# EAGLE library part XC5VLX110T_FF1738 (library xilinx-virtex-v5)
xc5vlx110t_ff1738 edit this description Auto generated by make-symbol-device-package-bsdl.ulp Rev. 21 Source: xc5vlx110t_ff1738.bsd
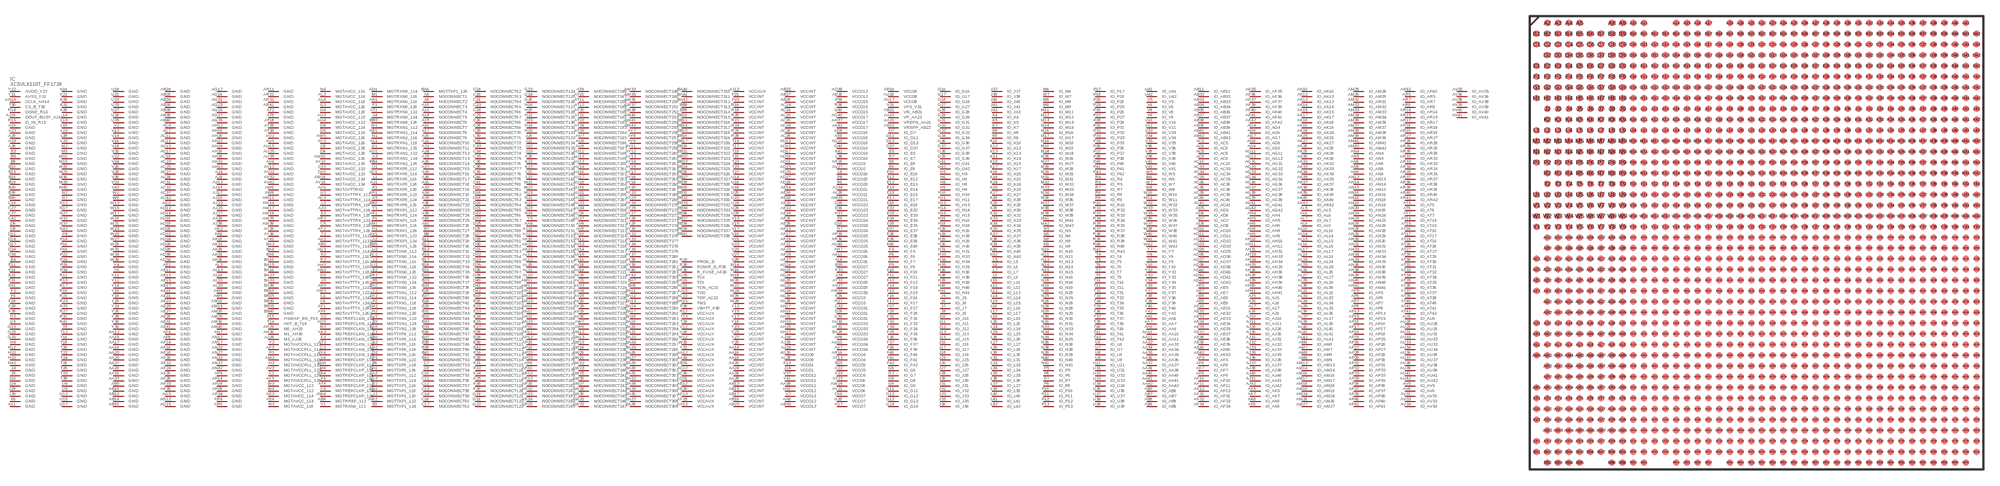
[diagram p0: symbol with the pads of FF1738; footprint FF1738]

Designator prefix IC

## XC5VLX110T_FF1738 (OC_FARNELL: unknown; OC_NEWARK: unknown)  [FF1738]
A2  MGTRXP1_124  pas
A3  MGTRXN1_124  pas
A4  MGTRXN0_124  pas
A5  MGTRXP0_124  pas
A8  NOCONNECT1  pas
A9  NOCONNECT2  pas
A10  NOCONNECT3  pas
A11  NOCONNECT4  pas
A14  NOCONNECT5  pas
A15  NOCONNECT6  pas
A16  NOCONNECT7  pas
A17  NOCONNECT8  pas
A19  GND  pwr
A20  NOCONNECT9  pas
A21  NOCONNECT10  pas
A22  NOCONNECT11  pas
A23  GND  pwr
A24  NOCONNECT12  pas
A25  NOCONNECT13  pas
A26  NOCONNECT14  pas
A27  NOCONNECT15  pas
A28  GND  pwr
A29  NOCONNECT16  pas
A30  NOCONNECT17  pas
A31  NOCONNECT18  pas
A32  NOCONNECT19  pas
A33  GND  pwr
A34  NOCONNECT20  pas
A35  NOCONNECT21  pas
A36  NOCONNECT22  pas
A37  NOCONNECT23  pas
A38  GND  pwr
A39  NOCONNECT24  pas
A40  NOCONNECT25  pas
A41  NOCONNECT26  pas
AA2  MGTTXP1_112  pas
AA3  MGTAVTTTX_1122  pas
AA4  NOCONNECT150  pas
AA5  MGTAVTTRXC  pas
AA6  IO_AA6
AA7  IO_AA7
AA8  VCCO12  pwr
AA9  IO_AA9
AA10  IO_AA10
AA11  IO_AA11
AA12  VCCAUX  pwr
AA13  GND  pwr
AA14  VCCINT  pwr
AA15  GND  pwr
AA16  VCCINT  pwr
AA17  GND  pwr
AA18  VCCINT  pwr
AA19  GND  pwr
AA20  VCCINT  pwr
AA21  VREFN_AA21  pas
AA22  VP_AA22  pas
AA23  GND  pwr
AA24  VCCINT  pwr
AA25  GND  pwr
AA26  VCCINT  pwr
AA27  GND  pwr
AA28  VCCINT  pwr
AA29  GND  pwr
AA30  VCCAUX  pwr
AA31  GND  pwr
AA32  IO_AA32
AA33  GND  pwr
AA34  IO_AA34
AA35  IO_AA35
AA36  IO_AA36
AA37  IO_AA37
AA38  VCCO11  pwr
AA39  IO_AA39
AA40  IO_AA40
AA41  IO_AA41
AA42  IO_AA42
AB2  MGTTXP0_114  pas
AB3  MGTAVTTTX_1141  pas
AB4  MGTRREF_112  pas
AB5  GND  pwr
AB6  IO_AB6
AB7  IO_AB7
AB8  IO_AB8
AB9  IO_AB9
AB10  GND  pwr
AB11  IO_AB11
AB12  GND  pwr
AB13  VCCINT  pwr
AB14  GND  pwr
AB15  VCCINT  pwr
AB16  GND  pwr
AB17  VCCINT  pwr
AB18  GND  pwr
AB19  VCCINT  pwr
AB20  GND  pwr
AB21  VN_AB21  pas
AB22  VREFP_AB22  pas
AB23  VCCINT  pwr
AB24  GND  pwr
AB25  VCCINT  pwr
AB26  GND  pwr
AB27  VCCINT  pwr
AB28  GND  pwr
AB29  VCCINT  pwr
AB30  GND  pwr
AB31  VCCAUX  pwr
AB32  IO_AB32
AB33  IO_AB33
AB34  IO_AB34
AB35  VCCO13  pwr
AB36  IO_AB36
AB37  IO_AB37
AB38  IO_AB38
AB39  IO_AB39
AB40  GND  pwr
AB41  IO_AB41
AB42  IO_AB42
AC1  MGTRXP0_114  pas
AC2  MGTTXN0_114  pas
AC3  MGTAVTTRX_114  pas
AC4  GND  pwr
AC5  IO_AC5
AC6  IO_AC6
AC7  GND  pwr
AC8  IO_AC8
AC9  IO_AC9
AC10  IO_AC10
AC11  GND  pwr
AC12  VCCAUX  pwr
AC13  GND  pwr
AC14  VCCINT  pwr
AC15  GND  pwr
AC16  VCCINT  pwr
AC17  GND  pwr
AC18  VCCINT  pwr
AC19  GND  pwr
AC20  VCCINT  pwr
AC21  TDN_AC21  pas
AC22  TDP_AC22  pas
AC23  GND  pwr
AC24  VCCINT  pwr
AC25  GND  pwr
AC26  VCCINT  pwr
AC27  GND  pwr
AC28  VCCINT  pwr
AC29  GND  pwr
AC30  VCCAUX  pwr
AC31  GND  pwr
AC32  GND  pwr
AC33  IO_AC33
AC34  IO_AC34
AC35  IO_AC35
AC36  IO_AC36
AC37  GND  pwr
AC38  IO_AC38
AC39  IO_AC39
AC40  IO_AC40
AC41  IO_AC41
AC42  GND  pwr
AD1  MGTRXN0_114  pas
AD2  GND  pwr
AD3  MGTREFCLKN_114  pas
AD4  MGTREFCLKP_114  pas
AD5  IO_AD5
AD6  IO_AD6
AD7  IO_AD7
AD8  IO_AD8
AD9  VCCO18  pwr
AD10  IO_AD10
AD11  IO_AD11
AD12  GND  pwr
AD13  VCCINT  pwr
AD14  GND  pwr
AD15  VCCINT  pwr
AD16  GND  pwr
AD17  VCCINT  pwr
AD18  GND  pwr
AD19  VCCINT  pwr
AD20  GND  pwr
AD21  VCCINT  pwr
AD22  GND  pwr
AD23  VCCINT  pwr
AD24  GND  pwr
AD25  VCCINT  pwr
AD26  GND  pwr
AD27  VCCINT  pwr
AD28  GND  pwr
AD29  VCCINT  pwr
AD30  GND  pwr
AD31  VCCAUX  pwr
AD32  IO_AD32
AD33  IO_AD33
AD34  GND  pwr
AD35  IO_AD35
AD36  IO_AD36
AD37  IO_AD37
AD38  IO_AD38
AD39  VCCO13  pwr
AD40  IO_AD40
AD41  IO_AD41
AD42  IO_AD42
AE1  MGTRXN1_114  pas
AE2  GND  pwr
AE3  MGTAVCC_114  pwr
AE4  MGTAVCC_114  pwr
AE5  IO_AE5
AE6  VCCO18  pwr
AE7  IO_AE7
AE8  IO_AE8
AE9  IO_AE9
AE10  IO_AE10
AE11  GND  pwr
AE12  VCCAUX  pwr
AE13  GND  pwr
AE14  VCCINT  pwr
AE15  GND  pwr
AE16  VCCINT  pwr
AE17  GND  pwr
AE18  VCCINT  pwr
AE19  GND  pwr
AE20  VCCINT  pwr
AE21  GND  pwr
AE22  VCCINT  pwr
AE23  GND  pwr
AE24  VCCINT  pwr
AE25  GND  pwr
AE26  VCCINT  pwr
AE27  GND  pwr
AE28  VCCINT  pwr
AE29  GND  pwr
AE30  VCCAUX  pwr
AE31  GND  pwr
AE32  IO_AE32
AE33  IO_AE33
AE34  IO_AE34
AE35  IO_AE35
AE36  VCCO13  pwr
AE37  IO_AE37
AE38  IO_AE38
AE39  IO_AE39
AE40  IO_AE40
AE41  GND  pwr
AE42  IO_AE42
AF1  MGTRXP1_114  pas
AF2  MGTTXN1_114  pas
AF3  MGTAVCCPLL_114  pwr
AF4  GND  pwr
AF5  IO_AF5
AF6  IO_AF6
AF7  IO_AF7
AF8  GND  pwr
AF9  IO_AF9
AF10  IO_AF10
AF11  IO_AF11
AF12  IO_AF12
AF13  VCCAUX  pwr
AF14  GND  pwr
AF15  VCCINT  pwr
AF16  GND  pwr
AF17  VCCINT  pwr
AF18  GND  pwr
AF19  VCCINT  pwr
AF20  GND  pwr
AF21  VCCINT  pwr
AF22  GND  pwr
AF23  VCCINT  pwr
AF24  GND  pwr
AF25  VCCINT  pwr
AF26  GND  pwr
AF27  VCCINT  pwr
AF28  GND  pwr
AF29  VCCAUX  pwr
AF30  R_FUSE_AF30  pas
AF31  IO_AF31
AF32  IO_AF32
AF33  GND  pwr
AF34  IO_AF34
AF35  IO_AF35
AF36  IO_AF36
AF37  IO_AF37
AF38  GND  pwr
AF39  IO_AF39
AF40  IO_AF40
AF41  IO_AF41
AF42  IO_AF42
AG2  MGTTXP1_114  pas
AG3  MGTAVTTTX_1142  pas
AG4  IO_AG4
AG5  GND  pwr
AG6  IO_AG6
AG7  IO_AG7
AG8  IO_AG8
AG9  IO_AG9
AG10  VCCO18  pwr
AG11  IO_AG11
AG12  IO_AG12
AG13  GND  pwr
AG14  VCCINT  pwr
AG15  GND  pwr
AG16  VCCINT  pwr
AG17  GND  pwr
AG18  VCCINT  pwr
AG19  GND  pwr
AG20  VCCINT  pwr
AG21  GND  pwr
AG22  VCCINT  pwr
AG23  GND  pwr
AG24  VCCINT  pwr
AG25  GND  pwr
AG26  VCCINT  pwr
AG27  GND  pwr
AG28  VCCINT  pwr
AG29  TCK  in
AG30  VCCO0  pwr
AG31  IO_AG31
AG32  IO_AG32
AG33  IO_AG33
AG34  IO_AG34
AG35  GND  pwr
AG36  IO_AG36
AG37  IO_AG37
AG38  IO_AG38
AG39  IO_AG39
AG40  VCCO17  pwr
AG41  IO_AG41
AG42  IO_AG42
AH2  MGTTXP0_118  pas
AH3  MGTAVTTTX_1181  pas
AH4  IO_AH4
AH5  IO_AH5
AH6  IO_AH6
AH7  VCCO26  pwr
AH8  IO_AH8
AH9  IO_AH9
AH10  IO_AH10
AH11  IO_AH11
AH12  GND  pwr
AH13  VCCAUX  pwr
AH14  CCLK_AH14
AH15  TMS  in
AH16  TDI  in
AH17  VCCINT  pwr
AH18  GND  pwr
AH19  VCCINT  pwr
AH20  GND  pwr
AH21  VCCINT  pwr
AH22  GND  pwr
AH23  VCCINT  pwr
AH24  GND  pwr
AH25  VCCINT  pwr
AH26  GND  pwr
AH27  VCCINT  pwr
AH28  GND  pwr
AH29  M0_AH29  in
AH30  M1_AH30  in
AH31  IO_AH31
AH32  GND  pwr
AH33  IO_AH33
AH34  IO_AH34
AH35  IO_AH35
AH36  IO_AH36
AH37  VCCO17  pwr
AH38  IO_AH38
AH39  IO_AH39
AH40  IO_AH40
AH41  IO_AH41
AH42  GND  pwr
AJ1  MGTRXP0_118  pas
AJ2  MGTTXN0_118  pas
AJ3  MGTAVTTRX_118  pas
AJ4  GND  pwr
AJ5  IO_AJ5
AJ6  IO_AJ6
AJ7  IO_AJ7
AJ8  IO_AJ8
AJ9  GND  pwr
AJ10  IO_AJ10
AJ11  IO_AJ11
AJ12  VCCAUX  pwr
AJ13  GND  pwr
AJ14  GND  pwr
AJ15  TDO  out
AJ16  DOUT_BUSY_AJ16  out
AJ17  GND  pwr
AJ18  VCCINT  pwr
AJ19  GND  pwr
AJ20  VCCINT  pwr
AJ21  NOCONNECT151  pas
AJ22  NOCONNECT152  pas
AJ23  GND  pwr
AJ24  VCCINT  pwr
AJ25  GND  pwr
AJ26  IO_AJ26
AJ27  GND  pwr
AJ28  M2_AJ28  in
AJ29  GND  pwr
AJ30  IO_AJ30
AJ31  IO_AJ31
AJ32  IO_AJ32
AJ33  IO_AJ33
AJ34  VCCO21  pwr
AJ35  IO_AJ35
AJ36  IO_AJ36
AJ37  IO_AJ37
AJ38  IO_AJ38
AJ39  GND  pwr
AJ40  IO_AJ40
AJ41  IO_AJ41
AJ42  IO_AJ42
AK1  MGTRXN0_118  pas
AK2  GND  pwr
AK3  MGTREFCLKN_118  pas
AK4  MGTREFCLKP_118  pas
AK5  IO_AK5
AK6  GND  pwr
AK7  IO_AK7
AK8  IO_AK8
AK9  IO_AK9
AK10  IO_AK10
AK11  VCCO26  pwr
AK12  IO_AK12
AK13  IO_AK13
AK14  IO_AK14
AK15  IO_AK15
AK16  GND  pwr
AK17  IO_AK17
AK18  IO_AK18
AK19  IO_AK19
AK20  NOCONNECT153  pas
AK21  GND  pwr
AK22  NOCONNECT154  pas
AK23  NOCONNECT155  pas
AK24  IO_AK24
AK25  IO_AK25
AK26  GND  pwr
AK27  IO_AK27
AK28  IO_AK28
AK29  IO_AK29
AK30  IO_AK30
AK31  GND  pwr
AK32  IO_AK32
AK33  IO_AK33
AK34  IO_AK34
AK35  IO_AK35
AK36  GND  pwr
AK37  IO_AK37
AK38  IO_AK38
AK39  IO_AK39
AK40  IO_AK40
AK41  VCCO17  pwr
AK42  IO_AK42
AL1  MGTRXN1_118  pas
AL2  GND  pwr
AL3  MGTAVCC_118  pwr
AL4  MGTAVCC_118  pwr
AL5  IO_AL5
AL6  IO_AL6
AL7  IO_AL7
AL8  VCCO26  pwr
AL9  IO_AL9
AL10  IO_AL10
AL11  NOCONNECT156  pas
AL12  NOCONNECT157  pas
AL13  GND  pwr
AL14  IO_AL14
AL15  IO_AL15
AL16  IO_AL16
AL17  IO_AL17
AL18  GND  pwr
AL19  IO_AL19
AL20  NOCONNECT158  pas
AL21  NOCONNECT159  pas
AL22  NOCONNECT160  pas
AL23  GND  pwr
AL24  IO_AL24
AL25  IO_AL25
AL26  IO_AL26
AL27  IO_AL27
AL28  VCCO0  pwr
AL29  IO_AL29
AL30  IO_AL30
AL31  IO_AL31
AL32  IO_AL32
AL33  GND  pwr
AL34  IO_AL34
AL35  IO_AL35
AL36  IO_AL36
AL37  IO_AL37
AL38  VCCO21  pwr
AL39  IO_AL39
AL40  IO_AL40
AL41  IO_AL41
AL42  IO_AL42
AM1  MGTRXP1_118  pas
AM2  MGTTXN1_118  pas
AM3  MGTAVCCPLL_118  pwr
AM4  GND  pwr
AM5  GND  pwr
AM6  IO_AM6
AM7  IO_AM7
AM8  IO_AM8
AM9  IO_AM9
AM10  GND  pwr
AM11  NOCONNECT161  pas
AM12  NOCONNECT162  pas
AM13  IO_AM13
AM14  IO_AM14
AM15  GND  pwr
AM16  IO_AM16
AM17  IO_AM17
AM18  IO_AM18
AM19  IO_AM19
AM20  GND  pwr
AM21  NOCONNECT163  pas
AM22  NOCONNECT164  pas
AM23  NOCONNECT165  pas
AM24  IO_AM24
AM25  GND  pwr
AM26  IO_AM26
AM27  IO_AM27
AM28  IO_AM28
AM29  IO_AM29
AM30  GND  pwr
AM31  IO_AM31
AM32  IO_AM32
AM33  IO_AM33
AM34  IO_AM34
AM35  VCCO21  pwr
AM36  IO_AM36
AM37  IO_AM37
AM38  IO_AM38
AM39  IO_AM39
AM40  GND  pwr
AM41  IO_AM41
AM42  IO_AM42
AN2  MGTTXP1_118  pas
AN3  MGTAVTTTX_1182  pas
AN4  IO_AN4
AN5  IO_AN5
AN6  IO_AN6
AN7  GND  pwr
AN8  IO_AN8
AN9  IO_AN9
AN10  NOCONNECT166  pas
AN11  NOCONNECT167  pas
AN12  GND  pwr
AN13  IO_AN13
AN14  IO_AN14
AN15  IO_AN15
AN16  IO_AN16
AN17  GND  pwr
AN18  IO_AN18
AN19  IO_AN19
AN20  IO_AN20
AN21  NOCONNECT168  pas
AN22  GND  pwr
AN23  NOCONNECT169  pas
AN24  IO_AN24
AN25  IO_AN25
AN26  IO_AN26
AN27  GND  pwr
AN28  IO_AN28
AN29  IO_AN29
AN30  IO_AN30
AN31  IO_AN31
AN32  GND  pwr
AN33  IO_AN33
AN34  IO_AN34
AN35  IO_AN35
AN36  IO_AN36
AN37  GND  pwr
AN38  IO_AN38
AN39  IO_AN39
AN40  IO_AN40
AN41  IO_AN41
AN42  GND  pwr
AP2  MGTTXP0_122  pas
AP3  MGTAVTTTX_1221  pas
AP4  GND  pwr
AP5  IO_AP5
AP6  IO_AP6
AP7  IO_AP7
AP8  IO_AP8
AP9  VCCO34  pwr
AP10  NOCONNECT170  pas
AP11  NOCONNECT171  pas
AP12  NOCONNECT172  pas
AP13  IO_AP13
AP14  GND  pwr
AP15  IO_AP15
AP16  IO_AP16
AP17  IO_AP17
AP18  IO_AP18
AP19  VCCO8  pwr
AP20  NOCONNECT173  pas
AP21  NOCONNECT174  pas
AP22  NOCONNECT175  pas
AP23  NOCONNECT176  pas
AP24  GND  pwr
AP25  IO_AP25
AP26  IO_AP26
AP27  IO_AP27
AP28  IO_AP28
AP29  GND  pwr
AP30  IO_AP30
AP31  IO_AP31
AP32  IO_AP32
AP33  IO_AP33
AP34  GND  pwr
AP35  IO_AP35
AP36  IO_AP36
AP37  IO_AP37
AP38  IO_AP38
AP39  VCCO25  pwr
AP40  IO_AP40
AP41  IO_AP41
AP42  IO_AP42
AR1  MGTRXP0_122  pas
AR2  MGTTXN0_122  pas
AR3  MGTAVTTRX_122  pas
AR4  GND  pwr
AR5  IO_AR5
AR6  GND  pwr
AR7  IO_AR7
AR8  IO_AR8
AR9  NOCONNECT177  pas
AR10  NOCONNECT178  pas
AR11  GND  pwr
AR12  NOCONNECT179  pas
AR13  NOCONNECT180  pas
AR14  IO_AR14
AR15  IO_AR15
AR16  VCCO4  pwr
AR17  IO_AR17
AR18  IO_AR18
AR19  IO_AR19
AR20  NOCONNECT181  pas
AR21  GND  pwr
AR22  NOCONNECT182  pas
AR23  NOCONNECT183  pas
AR24  NOCONNECT184  pas
AR25  NOCONNECT185  pas
AR26  VCCO2  pwr
AR27  IO_AR27
AR28  IO_AR28
AR29  IO_AR29
AR30  IO_AR30
AR31  GND  pwr
AR32  IO_AR32
AR33  IO_AR33
AR34  IO_AR34
AR35  IO_AR35
AR36  VCCO25  pwr
AR37  IO_AR37
AR38  IO_AR38
AR39  IO_AR39
AR40  IO_AR40
AR41  GND  pwr
AR42  IO_AR42
AT1  MGTRXN0_122  pas
AT2  GND  pwr
AT3  MGTREFCLKN_122  pas
AT4  MGTREFCLKP_122  pas
AT5  IO_AT5
AT6  IO_AT6
AT7  IO_AT7
AT8  GND  pwr
AT9  NOCONNECT186  pas
AT10  NOCONNECT187  pas
AT11  NOCONNECT188  pas
AT12  NOCONNECT189  pas
AT13  VCCO4  pwr
AT14  IO_AT14
AT15  IO_AT15
AT16  IO_AT16
AT17  IO_AT17
AT18  GND  pwr
AT19  IO_AT19
AT20  NOCONNECT190  pas
AT21  NOCONNECT191  pas
AT22  NOCONNECT192  pas
AT23  VCCO6  pwr
AT24  NOCONNECT193  pas
AT25  NOCONNECT194  pas
AT26  IO_AT26
AT27  IO_AT27
AT28  GND  pwr
AT29  IO_AT29
AT30  IO_AT30
AT31  IO_AT31
AT32  IO_AT32
AT33  VCCO29  pwr
AT34  IO_AT34
AT35  IO_AT35
AT36  IO_AT36
AT37  IO_AT37
AT38  GND  pwr
AT39  IO_AT39
AT40  IO_AT40
AT41  IO_AT41
AT42  IO_AT42
AU1  MGTRXN1_122  pas
AU2  GND  pwr
AU3  MGTAVCC_122  pwr
AU4  MGTAVCC_122  pwr
AU5  GND  pwr
AU6  IO_AU6
AU7  NOCONNECT195  pas
AU8  NOCONNECT196  pas
AU9  NOCONNECT197  pas
AU10  VCCO34  pwr
AU11  NOCONNECT198  pas
AU12  NOCONNECT199  pas
AU13  NOCONNECT200  pas
AU14  NOCONNECT201  pas
AU15  GND  pwr
AU16  NOCONNECT202  pas
AU17  NOCONNECT203  pas
AU18  NOCONNECT204  pas
AU19  NOCONNECT205  pas
AU20  VCCO8  pwr
AU21  NOCONNECT206  pas
AU22  NOCONNECT207  pas
AU23  NOCONNECT208  pas
AU24  NOCONNECT209  pas
AU25  GND  pwr
AU26  NOCONNECT210  pas
AU27  NOCONNECT211  pas
AU28  IO_AU28
AU29  IO_AU29
AU30  VCCO33  pwr
AU31  IO_AU31
AU32  IO_AU32
AU33  IO_AU33
AU34  IO_AU34
AU35  GND  pwr
AU36  IO_AU36
AU37  IO_AU37
AU38  IO_AU38
AU39  IO_AU39
AU40  VCCO25  pwr
AU41  IO_AU41
AU42  IO_AU42
AV1  MGTRXP1_122  pas
AV2  MGTTXN1_122  pas
AV3  MGTAVCCPLL_122  pwr
AV4  GND  pwr
AV5  IO_AV5
AV6  IO_AV6
AV7  VCCO34  pwr
AV8  NOCONNECT212  pas
AV9  NOCONNECT213  pas
AV10  NOCONNECT214  pas
AV11  NOCONNECT215  pas
AV12  GND  pwr
AV13  NOCONNECT216  pas
AV14  NOCONNECT217  pas
AV15  NOCONNECT218  pas
AV16  NOCONNECT219  pas
AV17  VCCO8  pwr
AV18  NOCONNECT220  pas
AV19  NOCONNECT221  pas
AV20  NOCONNECT222  pas
AV21  NOCONNECT223  pas
AV22  GND  pwr
AV23  NOCONNECT224  pas
AV24  NOCONNECT225  pas
AV25  NOCONNECT226  pas
AV26  NOCONNECT227  pas
AV27  VCCO2  pwr
AV28  NOCONNECT228  pas
AV29  NOCONNECT229  pas
AV30  NOCONNECT230  pas
AV31  IO_AV31
AV32  GND  pwr
AV33  IO_AV33
AV34  IO_AV34
AV35  IO_AV35
AV36  IO_AV36
AV37  VCCO29  pwr
AV38  IO_AV38
AV39  IO_AV39
AV40  IO_AV40
AV41  IO_AV41
AV42  GND  pwr
AW2  MGTTXP1_122  pas
AW3  MGTAVTTTX_1222  pas
AW4  MGTREFCLKP_126  pas
AW5  MGTAVCC_126  pwr
AW6  GND  pwr
AW7  NOCONNECT231  pas
AW8  GND  pwr
AW9  NOCONNECT232  pas
AW10  MGTAVCC_130  pwr
AW11  GND  pwr
AW12  NOCONNECT233  pas
AW13  NOCONNECT234  pas
AW14  GND  pwr
AW15  NOCONNECT235  pas
AW16  MGTAVCC_134  pwr
AW17  GND  pwr
AW18  NOCONNECT236  pas
AW19  GND  pwr
AW20  NOCONNECT237  pas
AW21  NOCONNECT238  pas
AW22  NOCONNECT239  pas
AW23  NOCONNECT240  pas
AW24  VCCO6  pwr
AW25  NOCONNECT241  pas
AW26  NOCONNECT242  pas
AW27  NOCONNECT243  pas
AW28  NOCONNECT244  pas
AW29  GND  pwr
AW30  NOCONNECT245  pas
AW31  NOCONNECT246  pas
AW32  NOCONNECT247  pas
AW33  NOCONNECT248  pas
AW34  VCCO29  pwr
AW35  NOCONNECT249  pas
AW36  NOCONNECT250  pas
AW37  NOCONNECT251  pas
AW38  NOCONNECT252  pas
AW39  GND  pwr
AW40  NOCONNECT253  pas
AW41  NOCONNECT254  pas
AW42  NOCONNECT255  pas
AY1  MGTAVTTTX_1261  pas
AY2  MGTAVTTRX_126  pas
AY3  MGTAVCC_126  pwr
AY4  MGTREFCLKN_126  pas
AY5  MGTAVCCPLL_126  pwr
AY6  MGTAVTTTX_1262  pas
AY7  NOCONNECT256  pas
AY8  NOCONNECT257  pas
AY9  NOCONNECT258  pas
AY10  MGTAVCC_130  pwr
AY11  NOCONNECT259  pas
AY12  NOCONNECT260  pas
AY13  NOCONNECT261  pas
AY14  NOCONNECT262  pas
AY15  NOCONNECT263  pas
AY16  MGTAVCC_134  pwr
AY17  NOCONNECT264  pas
AY18  NOCONNECT265  pas
AY19  NOCONNECT266  pas
AY20  NOCONNECT267  pas
AY21  VCCO6  pwr
AY22  NOCONNECT268  pas
AY23  NOCONNECT269  pas
AY24  NOCONNECT270  pas
AY25  NOCONNECT271  pas
AY26  GND  pwr
AY27  NOCONNECT272  pas
AY28  NOCONNECT273  pas
AY29  NOCONNECT274  pas
AY30  NOCONNECT275  pas
AY31  VCCO33  pwr
AY32  NOCONNECT276  pas
AY33  NOCONNECT277  pas
AY34  NOCONNECT278  pas
AY35  NOCONNECT279  pas
AY36  GND  pwr
AY37  NOCONNECT280  pas
AY38  NOCONNECT281  pas
AY39  NOCONNECT282  pas
AY40  NOCONNECT283  pas
AY41  GND  pwr
AY42  NOCONNECT284  pas
B1  MGTTXP1_124  pas
B2  MGTTXN1_124  pas
B3  GND  pwr
B4  GND  pwr
B5  MGTTXN0_124  pas
B6  MGTTXP0_124  pas
B7  NOCONNECT27  pas
B8  NOCONNECT28  pas
B9  GND  pwr
B10  GND  pwr
B11  NOCONNECT29  pas
B12  NOCONNECT30  pas
B13  NOCONNECT31  pas
B14  NOCONNECT32  pas
B15  GND  pwr
B16  GND  pwr
B17  NOCONNECT33  pas
B18  NOCONNECT34  pas
B19  GND  pwr
B20  GND  pwr
B21  NOCONNECT35  pas
B22  NOCONNECT36  pas
B23  NOCONNECT37  pas
B24  NOCONNECT38  pas
B25  VCCO5  pwr
B26  NOCONNECT39  pas
B27  NOCONNECT40  pas
B28  NOCONNECT41  pas
B29  NOCONNECT42  pas
B30  GND  pwr
B31  NOCONNECT43  pas
B32  NOCONNECT44  pas
B33  NOCONNECT45  pas
B34  NOCONNECT46  pas
B35  VCCO27  pwr
B36  NOCONNECT47  pas
B37  NOCONNECT48  pas
B38  NOCONNECT49  pas
B39  NOCONNECT50  pas
B40  GND  pwr
B41  NOCONNECT51  pas
B42  NOCONNECT52  pas
BA1  MGTTXP0_126  pas
BA2  MGTTXN0_126  pas
BA3  GND  pwr
BA4  GND  pwr
BA5  MGTTXN1_126  pas
BA6  MGTTXP1_126  pas
BA7  NOCONNECT285  pas
BA8  NOCONNECT286  pas
BA9  GND  pwr
BA10  GND  pwr
BA11  NOCONNECT287  pas
BA12  NOCONNECT288  pas
BA13  NOCONNECT289  pas
BA14  NOCONNECT290  pas
BA15  GND  pwr
BA16  GND  pwr
BA17  NOCONNECT291  pas
BA18  NOCONNECT292  pas
BA19  NOCONNECT293  pas
BA20  NOCONNECT294  pas
BA21  NOCONNECT295  pas
BA22  NOCONNECT296  pas
BA23  GND  pwr
BA24  NOCONNECT297  pas
BA25  NOCONNECT298  pas
BA26  NOCONNECT299  pas
BA27  NOCONNECT300  pas
BA28  VCCO33  pwr
BA29  NOCONNECT301  pas
BA30  NOCONNECT302  pas
BA31  NOCONNECT303  pas
BA32  NOCONNECT304  pas
BA33  GND  pwr
BA34  NOCONNECT305  pas
BA35  NOCONNECT306  pas
BA36  NOCONNECT307  pas
BA37  NOCONNECT308  pas
BA38  GND  pwr
BA39  NOCONNECT309  pas
BA40  NOCONNECT310  pas
BA41  NOCONNECT311  pas
BA42  NOCONNECT312  pas
BB2  MGTRXP0_126  pas
BB3  MGTRXN0_126  pas
BB4  MGTRXN1_126  pas
BB5  MGTRXP1_126  pas
BB8  NOCONNECT313  pas
BB9  NOCONNECT314  pas
BB10  NOCONNECT315  pas
BB11  NOCONNECT316  pas
BB14  NOCONNECT317  pas
BB15  NOCONNECT318  pas
BB16  NOCONNECT319  pas
BB17  NOCONNECT320  pas
BB19  GND  pwr
BB20  NOCONNECT321  pas
BB21  NOCONNECT322  pas
BB22  NOCONNECT323  pas
BB23  NOCONNECT324  pas
BB24  NOCONNECT325  pas
BB25  GND  pwr
BB26  NOCONNECT326  pas
BB27  NOCONNECT327  pas
BB28  NOCONNECT328  pas
BB29  NOCONNECT329  pas
BB30  GND  pwr
BB31  NOCONNECT330  pas
BB32  NOCONNECT331  pas
BB33  NOCONNECT332  pas
BB34  NOCONNECT333  pas
BB35  GND  pwr
BB36  NOCONNECT334  pas
BB37  NOCONNECT335  pas
BB38  NOCONNECT336  pas
BB39  NOCONNECT337  pas
BB40  GND  pwr
BB41  NOCONNECT338  pas
C1  MGTAVTTTX_1241  pas
C2  MGTAVCCPLL_124  pwr
C3  MGTREFCLKN_124  pas
C4  MGTREFCLKP_124  pas
C5  MGTAVTTRX_124  pas
C6  MGTAVTTTX_1242  pas
C7  NOCONNECT53  pas
C8  NOCONNECT54  pas
C9  MGTAVCC_128  pwr
C10  NOCONNECT55  pas
C11  NOCONNECT56  pas
C12  NOCONNECT57  pas
C13  NOCONNECT58  pas
C14  NOCONNECT59  pas
C15  MGTAVCC_132  pwr
C16  NOCONNECT60  pas
C17  NOCONNECT61  pas
C18  NOCONNECT62  pas
C19  GND  pwr
C20  NOCONNECT63  pas
C21  NOCONNECT64  pas
C22  VCCO5  pwr
C23  NOCONNECT65  pas
C24  NOCONNECT66  pas
C25  NOCONNECT67  pas
C26  NOCONNECT68  pas
C27  GND  pwr
C28  NOCONNECT69  pas
C29  NOCONNECT70  pas
C30  NOCONNECT71  pas
C31  NOCONNECT72  pas
C32  VCCO31  pwr
C33  NOCONNECT73  pas
C34  NOCONNECT74  pas
C35  NOCONNECT75  pas
C36  NOCONNECT76  pas
C37  GND  pwr
C38  NOCONNECT77  pas
C39  NOCONNECT78  pas
C40  NOCONNECT79  pas
C41  NOCONNECT80  pas
C42  GND  pwr
D2  MGTTXP0_120  pas
D3  MGTAVTTTX_1201  pas
D4  MGTAVCC_124  pwr
D5  MGTAVCC_124  pwr
D6  GND  pwr
D7  IO_D7
D8  GND  pwr
D9  MGTAVCC_128  pwr
D10  NOCONNECT81  pas
D11  GND  pwr
D12  IO_D12
D13  IO_D13
D14  GND  pwr
D15  MGTAVCC_132  pwr
D16  NOCONNECT82  pas
D17  GND  pwr
D18  NOCONNECT83  pas
D19  VCCO7  pwr
D20  NOCONNECT84  pas
D21  NOCONNECT85  pas
D22  NOCONNECT86  pas
D23  NOCONNECT87  pas
D24  GND  pwr
D25  NOCONNECT88  pas
D26  NOCONNECT89  pas
D27  NOCONNECT90  pas
D28  NOCONNECT91  pas
D29  VCCO31  pwr
D30  NOCONNECT92  pas
D31  NOCONNECT93  pas
D32  NOCONNECT94  pas
D33  NOCONNECT95  pas
D34  GND  pwr
D35  NOCONNECT96  pas
D36  NOCONNECT97  pas
D37  IO_D37
D38  NOCONNECT98  pas
D39  VCCO23  pwr
D40  NOCONNECT99  pas
D41  NOCONNECT100  pas
D42  NOCONNECT101  pas
E1  MGTRXP0_120  pas
E2  MGTTXN0_120  pas
E3  MGTAVTTRX_120  pas
E4  GND  pwr
E5  IO_E5
E6  VCCO24  pwr
E7  IO_E7
E8  IO_E8
E9  IO_E9
E10  IO_E10
E11  GND  pwr
E12  IO_E12
E13  IO_E13
E14  IO_E14
E15  IO_E15
E16  GND  pwr
E17  IO_E17
E18  IO_E18
E19  NOCONNECT102  pas
E20  NOCONNECT103  pas
E21  GND  pwr
E22  NOCONNECT104  pas
E23  NOCONNECT105  pas
E24  NOCONNECT106  pas
E25  NOCONNECT107  pas
E26  VCCO3  pwr
E27  NOCONNECT108  pas
E28  NOCONNECT109  pas
E29  NOCONNECT110  pas
E30  NOCONNECT111  pas
E31  GND  pwr
E32  IO_E32
E33  IO_E33
E34  IO_E34
E35  IO_E35
E36  VCCO23  pwr
E37  IO_E37
E38  IO_E38
E39  IO_E39
E40  IO_E40
E41  GND  pwr
E42  NOCONNECT112  pas
F1  MGTRXN0_120  pas
F2  GND  pwr
F3  MGTREFCLKN_120  pas
F4  MGTREFCLKP_120  pas
F5  IO_F5
F6  IO_F6
F7  IO_F7
F8  GND  pwr
F9  IO_F9
F10  IO_F10
F11  IO_F11
F12  IO_F12
F13  VCCO1  pwr
F14  IO_F14
F15  IO_F15
F16  IO_F16
F17  IO_F17
F18  GND  pwr
F19  NOCONNECT113  pas
F20  NOCONNECT114  pas
F21  NOCONNECT115  pas
F22  NOCONNECT116  pas
F23  VCCO5  pwr
F24  NOCONNECT117  pas
F25  NOCONNECT118  pas
F26  NOCONNECT119  pas
F27  IO_F27
F28  GND  pwr
F29  IO_F29
F30  NOCONNECT120  pas
F31  IO_F31
F32  IO_F32
F33  VCCO27  pwr
F34  IO_F34
F35  IO_F35
F36  IO_F36
F37  IO_F37
F38  GND  pwr
F39  IO_F39
F40  IO_F40
F41  IO_F41
F42  IO_F42
G1  MGTRXN1_120  pas
G2  GND  pwr
G3  MGTAVCC_120  pwr
G4  MGTAVCC_120  pwr
G5  GND  pwr
G6  IO_G6
G7  IO_G7
G8  IO_G8
G9  IO_G9
G10  VCCO24  pwr
G11  IO_G11
G12  IO_G12
G13  IO_G13
G14  IO_G14
G15  GND  pwr
G16  IO_G16
G17  IO_G17
G18  IO_G18
G19  NOCONNECT121  pas
G20  VCCO7  pwr
G21  NOCONNECT122  pas
G22  NOCONNECT123  pas
G23  NOCONNECT124  pas
G24  NOCONNECT125  pas
G25  GND  pwr
G26  NOCONNECT126  pas
G27  IO_G27
G28  IO_G28
G29  IO_G29
G30  VCCO31  pwr
G31  IO_G31
G32  IO_G32
G33  IO_G33
G34  IO_G34
G35  GND  pwr
G36  IO_G36
G37  IO_G37
G38  IO_G38
G39  IO_G39
G40  VCCO19  pwr
G41  IO_G41
G42  IO_G42
H1  MGTRXP1_120  pas
H2  MGTTXN1_120  pas
H3  MGTAVCCPLL_120  pwr
H4  GND  pwr
H5  IO_H5
H6  IO_H6
H7  VCCO24  pwr
H8  IO_H8
H9  IO_H9
H10  IO_H10
H11  IO_H11
H12  GND  pwr
H13  IO_H13
H14  IO_H14
H15  IO_H15
H16  IO_H16
H17  VCCO7  pwr
H18  IO_H18
H19  NOCONNECT127  pas
H20  NOCONNECT128  pas
H21  NOCONNECT129  pas
H22  GND  pwr
H23  NOCONNECT130  pas
H24  NOCONNECT131  pas
H25  NOCONNECT132  pas
H26  IO_H26
H27  VCCO3  pwr
H28  IO_H28
H29  IO_H29
H30  IO_H30
H31  IO_H31
H32  GND  pwr
H33  IO_H33
H34  IO_H34
H35  IO_H35
H36  IO_H36
H37  VCCO23  pwr
H38  IO_H38
H39  IO_H39
H40  IO_H40
H41  IO_H41
H42  GND  pwr
J2  MGTTXP1_120  pas
J3  MGTAVTTTX_1202  pas
J4  GND  pwr
J5  IO_J5
J6  IO_J6
J7  IO_J7
J8  IO_J8
J9  GND  pwr
J10  IO_J10
J11  IO_J11
J12  IO_J12
J13  IO_J13
J14  VCCO1  pwr
J15  IO_J15
J16  IO_J16
J17  IO_J17
J18  IO_J18
J19  GND  pwr
J20  NOCONNECT133  pas
J21  NOCONNECT134  pas
J22  NOCONNECT135  pas
J23  NOCONNECT136  pas
J24  GND  pwr
J25  IO_J25
J26  IO_J26
J27  IO_J27
J28  IO_J28
J29  GND  pwr
J30  IO_J30
J31  IO_J31
J32  IO_J32
J33  IO_J33
J34  VCCO27  pwr
J35  IO_J35
J36  IO_J36
J37  IO_J37
J38  IO_J38
J39  GND  pwr
J40  IO_J40
J41  IO_J41
J42  IO_J42
K2  MGTTXP0_116  pas
K3  MGTAVTTTX_1161  pas
K4  IO_K4
K5  IO_K5
K6  GND  pwr
K7  IO_K7
K8  IO_K8
K9  IO_K9
K10  IO_K10
K11  GND  pwr
K12  IO_K12
K13  IO_K13
K14  IO_K14
K15  IO_K15
K16  GND  pwr
K17  IO_K17
K18  IO_K18
K19  IO_K19
K20  NOCONNECT137  pas
K21  GND  pwr
K22  NOCONNECT138  pas
K23  NOCONNECT139  pas
K24  IO_K24
K25  IO_K25
K26  GND  pwr
K27  IO_K27
K28  IO_K28
K29  IO_K29
K30  IO_K30
K31  GND  pwr
K32  IO_K32
K33  IO_K33
K34  IO_K34
K35  IO_K35
K36  GND  pwr
K37  IO_K37
K38  IO_K38
K39  IO_K39
K40  IO_K40
K41  VCCO19  pwr
K42  IO_K42
L1  MGTRXP0_116  pas
L2  MGTTXN0_116  pas
L3  MGTAVTTRX_116  pas
L4  GND  pwr
L5  IO_L5
L6  IO_L6
L7  IO_L7
L8  VCCO20  pwr
L9  IO_L9
L10  IO_L10
L11  IO_L11
L12  IO_L12
L13  GND  pwr
L14  IO_L14
L15  IO_L15
L16  IO_L16
L17  IO_L17
L18  GND  pwr
L19  IO_L19
L20  IO_L20
L21  NOCONNECT140  pas
L22  NOCONNECT141  pas
L23  GND  pwr
L24  IO_L24
L25  IO_L25
L26  IO_L26
L27  IO_L27
L28  GND  pwr
L29  IO_L29
L30  IO_L30
L31  IO_L31
L32  IO_L32
L33  GND  pwr
L34  IO_L34
L35  IO_L35
L36  IO_L36
L37  IO_L37
L38  VCCO19  pwr
L39  IO_L39
L40  IO_L40
L41  IO_L41
L42  IO_L42
M1  MGTRXN0_116  pas
M2  GND  pwr
M3  MGTREFCLKN_116  pas
M4  MGTREFCLKP_116  pas
M5  GND  pwr
M6  IO_M6
M7  IO_M7
M8  IO_M8
M9  IO_M9
M10  GND  pwr
M11  IO_M11
M12  IO_M12
M13  IO_M13
M14  IO_M14
M15  GND  pwr
M16  IO_M16
M17  IO_M17
M18  IO_M18
M19  IO_M19
M20  GND  pwr
M21  NOCONNECT142  pas
M22  NOCONNECT143  pas
M23  NOCONNECT144  pas
M24  IO_M24
M25  GND  pwr
M26  IO_M26
M27  IO_M27
M28  IO_M28
M29  IO_M29
M30  GND  pwr
M31  IO_M31
M32  IO_M32
M33  IO_M33
M34  IO_M34
M35  GND  pwr
M36  IO_M36
M37  IO_M37
M38  IO_M38
M39  IO_M39
M40  GND  pwr
M41  IO_M41
M42  IO_M42
N1  MGTRXN1_116  pas
N2  GND  pwr
N3  MGTAVCC_116  pwr
N4  MGTAVCC_116  pwr
N5  IO_N5
N6  IO_N6
N7  GND  pwr
N8  IO_N8
N9  IO_N9
N10  IO_N10
N11  IO_N11
N12  GND  pwr
N13  IO_N13
N14  IO_N14
N15  IO_N15
N16  IO_N16
N17  GND  pwr
N18  IO_N18
N19  IO_N19
N20  IO_N20
N21  NOCONNECT145  pas
N22  NOCONNECT146  pas
N23  NOCONNECT147  pas
N24  NOCONNECT148  pas
N25  IO_N25
N26  IO_N26
N27  GND  pwr
N28  IO_N28
N29  IO_N29
N30  IO_N30
N31  IO_N31
N32  GND  pwr
N33  IO_N33
N34  IO_N34
N35  IO_N35
N36  IO_N36
N37  GND  pwr
N38  IO_N38
N39  IO_N39
N40  IO_N40
N41  IO_N41
N42  GND  pwr
P1  MGTRXP1_116  pas
P2  MGTTXN1_116  pas
P3  MGTAVCCPLL_116  pwr
P4  GND  pwr
P5  IO_P5
P6  IO_P6
P7  IO_P7
P8  IO_P8
P9  VCCO20  pwr
P10  IO_P10
P11  IO_P11
P12  IO_P12
P13  IO_P13
P14  GND  pwr
P15  HSWAP_EN_P15  in
P16  GND  pwr
P17  IO_P17
P18  IO_P18
P19  GND  pwr
P20  IO_P20
P21  VCCINT  pwr
P22  GND  pwr
P23  VCCINT  pwr
P24  GND  pwr
P25  IO_P25
P26  IO_P26
P27  IO_P27
P28  IO_P28
P29  GND  pwr
P30  VBATT_P30  pas
P31  IO_P31
P32  IO_P32
P33  IO_P33
P34  GND  pwr
P35  IO_P35
P36  IO_P36
P37  IO_P37
P38  IO_P38
P39  VCCO15  pwr
P40  IO_P40
P41  IO_P41
P42  IO_P42
R2  MGTTXP1_116  pas
R3  MGTAVTTTX_1162  pas
R4  IO_R4
R5  IO_R5
R6  VCCO20  pwr
R7  IO_R7
R8  IO_R8
R9  IO_R9
R10  IO_R10
R11  GND  pwr
R12  VCCAUX  pwr
R13  GND  pwr
R14  DONE_R14
R15  D_IN_R15  in
R16  VCCINT  pwr
R17  GND  pwr
R18  VCCINT  pwr
R19  GND  pwr
R20  VCCINT  pwr
R21  GND  pwr
R22  VCCINT  pwr
R23  GND  pwr
R24  VCCINT  pwr
R25  GND  pwr
R26  VCCINT  pwr
R27  GND  pwr
R28  VCCINT  pwr
R29  PROG_B  in
R30  RDWR_B_R30  in
R31  GND  pwr
R32  IO_R32
R33  IO_R33
R34  IO_R34
R35  IO_R35
R36  VCCO15  pwr
R37  IO_R37
R38  IO_R38
R39  IO_R39
R40  IO_R40
R41  GND  pwr
R42  IO_R42
T2  MGTTXP0_112  pas
T3  MGTAVTTTX_1121  pas
T4  IO_T4
T5  IO_T5
T6  IO_T6
T7  IO_T7
T8  GND  pwr
T9  IO_T9
T10  IO_T10
T11  IO_T11
T12  GND  pwr
T13  VCCAUX  pwr
T14  INIT_B_T14
T15  VCCINT  pwr
T16  GND  pwr
T17  VCCINT  pwr
T18  GND  pwr
T19  VCCINT  pwr
T20  GND  pwr
T21  VCCINT  pwr
T22  GND  pwr
T23  VCCINT  pwr
T24  GND  pwr
T25  VCCINT  pwr
T26  GND  pwr
T27  VCCINT  pwr
T28  GND  pwr
T29  VCCAUX  pwr
T30  CS_B_T30  in
T31  IO_T31
T32  IO_T32
T33  GND  pwr
T34  IO_T34
T35  IO_T35
T36  IO_T36
T37  IO_T37
T38  GND  pwr
T39  IO_T39
T40  IO_T40
T41  IO_T41
T42  IO_T42
U1  MGTRXP0_112  pas
U2  MGTTXN0_112  pas
U3  MGTAVTTRX_112  pas
U4  GND  pwr
U5  GND  pwr
U6  IO_U6
U7  IO_U7
U8  IO_U8
U9  IO_U9
U10  VCCO12  pwr
U11  IO_U11
U12  VCCAUX  pwr
U13  GND  pwr
U14  VCCINT  pwr
U15  GND  pwr
U16  VCCINT  pwr
U17  GND  pwr
U18  VCCINT  pwr
U19  GND  pwr
U20  VCCINT  pwr
U21  GND  pwr
U22  VCCINT  pwr
U23  GND  pwr
U24  VCCINT  pwr
U25  GND  pwr
U26  VCCINT  pwr
U27  GND  pwr
U28  VCCINT  pwr
U29  GND  pwr
U30  VCCAUX  pwr
U31  IO_U31
U32  IO_U32
U33  IO_U33
U34  IO_U34
U35  GND  pwr
U36  IO_U36
U37  IO_U37
U38  IO_U38
U39  IO_U39
U40  VCCO15  pwr
U41  IO_U41
U42  IO_U42
V1  MGTRXN0_112  pas
V2  GND  pwr
V3  MGTREFCLKN_112  pas
V4  MGTREFCLKP_112  pas
V5  IO_V5
V6  IO_V6
V7  VCCO12  pwr
V8  IO_V8
V9  IO_V9
V10  IO_V10
V11  IO_V11
V12  GND  pwr
V13  VCCINT  pwr
V14  GND  pwr
V15  VCCINT  pwr
V16  GND  pwr
V17  VCCINT  pwr
V18  GND  pwr
V19  VCCINT  pwr
V20  GND  pwr
V21  VCCINT  pwr
V22  GND  pwr
V23  VCCINT  pwr
V24  GND  pwr
V25  VCCINT  pwr
V26  GND  pwr
V27  VCCINT  pwr
V28  GND  pwr
V29  VCCINT  pwr
V30  GND  pwr
V31  VFS_V31  pas
V32  GND  pwr
V33  IO_V33
V34  IO_V34
V35  IO_V35
V36  IO_V36
V37  VCCO11  pwr
V38  IO_V38
V39  IO_V39
V40  IO_V40
V41  IO_V41
V42  GND  pwr
W1  MGTRXN1_112  pas
W2  GND  pwr
W3  MGTAVCC_112  pwr
W4  MGTAVCC_112  pwr
W5  IO_W5
W6  IO_W6
W7  IO_W7
W8  IO_W8
W9  GND  pwr
W10  IO_W10
W11  IO_W11
W12  VCCAUX  pwr
W13  GND  pwr
W14  VCCINT  pwr
W15  GND  pwr
W16  VCCINT  pwr
W17  GND  pwr
W18  VCCINT  pwr
W19  GND  pwr
W20  VCCINT  pwr
W21  GND  pwr
W22  VCCINT  pwr
W23  GND  pwr
W24  VCCINT  pwr
W25  GND  pwr
W26  VCCINT  pwr
W27  GND  pwr
W28  VCCINT  pwr
W29  GND  pwr
W30  VCCAUX  pwr
W31  GND  pwr
W32  IO_W32
W33  IO_W33
W34  GND  pwr
W35  IO_W35
W36  IO_W36
W37  IO_W37
W38  IO_W38
W39  GND  pwr
W40  IO_W40
W41  IO_W41
W42  IO_W42
Y1  MGTRXP1_112  pas
Y2  MGTTXN1_112  pas
Y3  MGTAVCCPLL_112  pwr
Y4  GND  pwr
Y5  NOCONNECT149  pas
Y6  GND  pwr
Y7  IO_Y7
Y8  IO_Y8
Y9  IO_Y9
Y10  IO_Y10
Y11  GND  pwr
Y12  GND  pwr
Y13  VCCINT  pwr
Y14  GND  pwr
Y15  VCCINT  pwr
Y16  GND  pwr
Y17  VCCINT  pwr
Y18  GND  pwr
Y19  VCCINT  pwr
Y20  GND  pwr
Y21  AVSS_Y21  pwr
Y22  AVDD_Y22  pwr
Y23  VCCINT  pwr
Y24  GND  pwr
Y25  VCCINT  pwr
Y26  GND  pwr
Y27  VCCINT  pwr
Y28  GND  pwr
Y29  VCCINT  pwr
Y30  GND  pwr
Y31  VCCAUX  pwr
Y32  IO_Y32
Y33  IO_Y33
Y34  IO_Y34
Y35  IO_Y35
Y36  GND  pwr
Y37  IO_Y37
Y38  IO_Y38
Y39  IO_Y39
Y40  IO_Y40
Y41  VCCO11  pwr
Y42  IO_Y42

## Footprint FF1738 (pad centres in mm)
xc5vlx110t_ff1738 edit this description Auto generated by make-symbol-device-package-bsdl.ulp Rev. 19 Source: xc5vlx110t_ff1738.bsd http://www.xilinx.com/support/documentation/package_specs/ff1738.pdf
smd 0.6 x 0.6: A2 -19.5,20.5; A3 -18.5,20.5; A4 -17.5,20.5; A5 -16.5,20.5; A8 -13.5,20.5; A9 -12.5,20.5; A10 -11.5,20.5; A11 -10.5,20.5; A14 -7.5,20.5; A15 -6.5,20.5; A16 -5.5,20.5; A17 -4.5,20.5; A19 -2.5,20.5; A20 -1.5,20.5; A21 -0.5,20.5; A22 0.5,20.5; A23 1.5,20.5; A24 2.5,20.5; A25 3.5,20.5; A26 4.5,20.5; A27 5.5,20.5; A28 6.5,20.5; A29 7.5,20.5; A30 8.5,20.5; A31 9.5,20.5; A32 10.5,20.5; A33 11.5,20.5; A34 12.5,20.5; A35 13.5,20.5; A36 14.5,20.5; A37 15.5,20.5; A38 16.5,20.5; A39 17.5,20.5; A40 18.5,20.5; A41 19.5,20.5; AA2 -19.5,0.5; AA3 -18.5,0.5; AA4 -17.5,0.5; AA5 -16.5,0.5; AA6 -15.5,0.5; AA7 -14.5,0.5; AA8 -13.5,0.5; AA9 -12.5,0.5; AA10 -11.5,0.5; AA11 -10.5,0.5; AA12 -9.5,0.5; AA13 -8.5,0.5; AA14 -7.5,0.5; AA15 -6.5,0.5; AA16 -5.5,0.5; AA17 -4.5,0.5; AA18 -3.5,0.5; AA19 -2.5,0.5; AA20 -1.5,0.5; AA21 -0.5,0.5; AA22 0.5,0.5; AA23 1.5,0.5; AA24 2.5,0.5; AA25 3.5,0.5; AA26 4.5,0.5; AA27 5.5,0.5; AA28 6.5,0.5; AA29 7.5,0.5; AA30 8.5,0.5; AA31 9.5,0.5; AA32 10.5,0.5; AA33 11.5,0.5; AA34 12.5,0.5; AA35 13.5,0.5; AA36 14.5,0.5; AA37 15.5,0.5; AA38 16.5,0.5; AA39 17.5,0.5; AA40 18.5,0.5; AA41 19.5,0.5; AA42 20.5,0.5; AB2 -19.5,-0.5; AB3 -18.5,-0.5; AB4 -17.5,-0.5; AB5 -16.5,-0.5; AB6 -15.5,-0.5; AB7 -14.5,-0.5; AB8 -13.5,-0.5; AB9 -12.5,-0.5; AB10 -11.5,-0.5; AB11 -10.5,-0.5; AB12 -9.5,-0.5; AB13 -8.5,-0.5; AB14 -7.5,-0.5; AB15 -6.5,-0.5; AB16 -5.5,-0.5; AB17 -4.5,-0.5; AB18 -3.5,-0.5; AB19 -2.5,-0.5; AB20 -1.5,-0.5; AB21 -0.5,-0.5; AB22 0.5,-0.5; AB23 1.5,-0.5; AB24 2.5,-0.5; AB25 3.5,-0.5; AB26 4.5,-0.5; AB27 5.5,-0.5; AB28 6.5,-0.5; AB29 7.5,-0.5; AB30 8.5,-0.5; AB31 9.5,-0.5; AB32 10.5,-0.5; AB33 11.5,-0.5; AB34 12.5,-0.5; AB35 13.5,-0.5; AB36 14.5,-0.5; AB37 15.5,-0.5; AB38 16.5,-0.5; AB39 17.5,-0.5; AB40 18.5,-0.5; AB41 19.5,-0.5; AB42 20.5,-0.5; AC1 -20.5,-1.5; AC2 -19.5,-1.5; AC3 -18.5,-1.5; AC4 -17.5,-1.5; AC5 -16.5,-1.5; AC6 -15.5,-1.5; AC7 -14.5,-1.5; AC8 -13.5,-1.5; AC9 -12.5,-1.5; AC10 -11.5,-1.5; AC11 -10.5,-1.5; AC12 -9.5,-1.5; AC13 -8.5,-1.5; AC14 -7.5,-1.5; AC15 -6.5,-1.5; AC16 -5.5,-1.5; AC17 -4.5,-1.5; AC18 -3.5,-1.5; AC19 -2.5,-1.5; AC20 -1.5,-1.5; AC21 -0.5,-1.5; AC22 0.5,-1.5; AC23 1.5,-1.5; AC24 2.5,-1.5; AC25 3.5,-1.5; AC26 4.5,-1.5; AC27 5.5,-1.5; AC28 6.5,-1.5; AC29 7.5,-1.5; AC30 8.5,-1.5; AC31 9.5,-1.5; AC32 10.5,-1.5; AC33 11.5,-1.5; AC34 12.5,-1.5; AC35 13.5,-1.5; AC36 14.5,-1.5; AC37 15.5,-1.5; AC38 16.5,-1.5; AC39 17.5,-1.5; AC40 18.5,-1.5; AC41 19.5,-1.5; AC42 20.5,-1.5; AD1 -20.5,-2.5; AD2 -19.5,-2.5; AD3 -18.5,-2.5; AD4 -17.5,-2.5; AD5 -16.5,-2.5; AD6 -15.5,-2.5; AD7 -14.5,-2.5; AD8 -13.5,-2.5; AD9 -12.5,-2.5; AD10 -11.5,-2.5; AD11 -10.5,-2.5; AD12 -9.5,-2.5; AD13 -8.5,-2.5; AD14 -7.5,-2.5; AD15 -6.5,-2.5; AD16 -5.5,-2.5; AD17 -4.5,-2.5; AD18 -3.5,-2.5; AD19 -2.5,-2.5; AD20 -1.5,-2.5; AD21 -0.5,-2.5; AD22 0.5,-2.5; AD23 1.5,-2.5; AD24 2.5,-2.5; AD25 3.5,-2.5; AD26 4.5,-2.5; AD27 5.5,-2.5; AD28 6.5,-2.5; AD29 7.5,-2.5; AD30 8.5,-2.5; AD31 9.5,-2.5; AD32 10.5,-2.5; AD33 11.5,-2.5; AD34 12.5,-2.5; AD35 13.5,-2.5; AD36 14.5,-2.5; AD37 15.5,-2.5; AD38 16.5,-2.5; AD39 17.5,-2.5; AD40 18.5,-2.5; AD41 19.5,-2.5; AD42 20.5,-2.5; AE1 -20.5,-3.5; AE2 -19.5,-3.5; AE3 -18.5,-3.5; AE4 -17.5,-3.5; AE5 -16.5,-3.5; AE6 -15.5,-3.5; AE7 -14.5,-3.5; AE8 -13.5,-3.5; AE9 -12.5,-3.5; AE10 -11.5,-3.5; AE11 -10.5,-3.5; AE12 -9.5,-3.5; AE13 -8.5,-3.5; AE14 -7.5,-3.5; AE15 -6.5,-3.5; AE16 -5.5,-3.5; AE17 -4.5,-3.5; AE18 -3.5,-3.5; AE19 -2.5,-3.5; AE20 -1.5,-3.5; AE21 -0.5,-3.5; AE22 0.5,-3.5; AE23 1.5,-3.5; AE24 2.5,-3.5; AE25 3.5,-3.5; AE26 4.5,-3.5; AE27 5.5,-3.5; AE28 6.5,-3.5; AE29 7.5,-3.5; AE30 8.5,-3.5; AE31 9.5,-3.5; AE32 10.5,-3.5; AE33 11.5,-3.5; AE34 12.5,-3.5; AE35 13.5,-3.5; AE36 14.5,-3.5; AE37 15.5,-3.5; AE38 16.5,-3.5; AE39 17.5,-3.5; AE40 18.5,-3.5; AE41 19.5,-3.5; AE42 20.5,-3.5; AF1 -20.5,-4.5; AF2 -19.5,-4.5; AF3 -18.5,-4.5; AF4 -17.5,-4.5; AF5 -16.5,-4.5; AF6 -15.5,-4.5; AF7 -14.5,-4.5; AF8 -13.5,-4.5; AF9 -12.5,-4.5; AF10 -11.5,-4.5; AF11 -10.5,-4.5; AF12 -9.5,-4.5; AF13 -8.5,-4.5; AF14 -7.5,-4.5; AF15 -6.5,-4.5; AF16 -5.5,-4.5; AF17 -4.5,-4.5; AF18 -3.5,-4.5; AF19 -2.5,-4.5; AF20 -1.5,-4.5; AF21 -0.5,-4.5; AF22 0.5,-4.5; AF23 1.5,-4.5; AF24 2.5,-4.5; AF25 3.5,-4.5; AF26 4.5,-4.5; AF27 5.5,-4.5; AF28 6.5,-4.5; AF29 7.5,-4.5; AF30 8.5,-4.5; AF31 9.5,-4.5; AF32 10.5,-4.5; AF33 11.5,-4.5; AF34 12.5,-4.5; AF35 13.5,-4.5; AF36 14.5,-4.5; AF37 15.5,-4.5; AF38 16.5,-4.5; AF39 17.5,-4.5; AF40 18.5,-4.5; AF41 19.5,-4.5; AF42 20.5,-4.5; AG2 -19.5,-5.5; AG3 -18.5,-5.5; AG4 -17.5,-5.5; AG5 -16.5,-5.5; AG6 -15.5,-5.5; AG7 -14.5,-5.5; AG8 -13.5,-5.5; AG9 -12.5,-5.5; AG10 -11.5,-5.5; AG11 -10.5,-5.5; AG12 -9.5,-5.5; AG13 -8.5,-5.5; AG14 -7.5,-5.5; AG15 -6.5,-5.5; AG16 -5.5,-5.5; AG17 -4.5,-5.5; AG18 -3.5,-5.5; AG19 -2.5,-5.5; AG20 -1.5,-5.5; AG21 -0.5,-5.5; AG22 0.5,-5.5; AG23 1.5,-5.5; AG24 2.5,-5.5; AG25 3.5,-5.5; AG26 4.5,-5.5; AG27 5.5,-5.5; AG28 6.5,-5.5; AG29 7.5,-5.5; AG30 8.5,-5.5; AG31 9.5,-5.5; AG32 10.5,-5.5; AG33 11.5,-5.5; AG34 12.5,-5.5; AG35 13.5,-5.5; AG36 14.5,-5.5; AG37 15.5,-5.5; AG38 16.5,-5.5; AG39 17.5,-5.5; AG40 18.5,-5.5; AG41 19.5,-5.5; AG42 20.5,-5.5; AH2 -19.5,-6.5; AH3 -18.5,-6.5; AH4 -17.5,-6.5; AH5 -16.5,-6.5; AH6 -15.5,-6.5; AH7 -14.5,-6.5; AH8 -13.5,-6.5; AH9 -12.5,-6.5; AH10 -11.5,-6.5; AH11 -10.5,-6.5; AH12 -9.5,-6.5; AH13 -8.5,-6.5; AH14 -7.5,-6.5; AH15 -6.5,-6.5; AH16 -5.5,-6.5; AH17 -4.5,-6.5; AH18 -3.5,-6.5; AH19 -2.5,-6.5; AH20 -1.5,-6.5; AH21 -0.5,-6.5; AH22 0.5,-6.5; AH23 1.5,-6.5; AH24 2.5,-6.5; AH25 3.5,-6.5; AH26 4.5,-6.5; AH27 5.5,-6.5; AH28 6.5,-6.5; AH29 7.5,-6.5; AH30 8.5,-6.5; AH31 9.5,-6.5; AH32 10.5,-6.5; AH33 11.5,-6.5; AH34 12.5,-6.5; AH35 13.5,-6.5; AH36 14.5,-6.5; AH37 15.5,-6.5; AH38 16.5,-6.5; AH39 17.5,-6.5; AH40 18.5,-6.5; AH41 19.5,-6.5; AH42 20.5,-6.5; AJ1 -20.5,-7.5; AJ2 -19.5,-7.5; AJ3 -18.5,-7.5; AJ4 -17.5,-7.5; AJ5 -16.5,-7.5; AJ6 -15.5,-7.5; AJ7 -14.5,-7.5; AJ8 -13.5,-7.5; AJ9 -12.5,-7.5; AJ10 -11.5,-7.5; AJ11 -10.5,-7.5; AJ12 -9.5,-7.5; AJ13 -8.5,-7.5; AJ14 -7.5,-7.5; AJ15 -6.5,-7.5; AJ16 -5.5,-7.5; AJ17 -4.5,-7.5; AJ18 -3.5,-7.5; AJ19 -2.5,-7.5; AJ20 -1.5,-7.5; AJ21 -0.5,-7.5; AJ22 0.5,-7.5; AJ23 1.5,-7.5; AJ24 2.5,-7.5; AJ25 3.5,-7.5; AJ26 4.5,-7.5; AJ27 5.5,-7.5; AJ28 6.5,-7.5; AJ29 7.5,-7.5; AJ30 8.5,-7.5; AJ31 9.5,-7.5; AJ32 10.5,-7.5; AJ33 11.5,-7.5; AJ34 12.5,-7.5; AJ35 13.5,-7.5; AJ36 14.5,-7.5; AJ37 15.5,-7.5; AJ38 16.5,-7.5; AJ39 17.5,-7.5; AJ40 18.5,-7.5; AJ41 19.5,-7.5; AJ42 20.5,-7.5; AK1 -20.5,-8.5; AK2 -19.5,-8.5; AK3 -18.5,-8.5; AK4 -17.5,-8.5; AK5 -16.5,-8.5; AK6 -15.5,-8.5; AK7 -14.5,-8.5; AK8 -13.5,-8.5; AK9 -12.5,-8.5; AK10 -11.5,-8.5; AK11 -10.5,-8.5; AK12 -9.5,-8.5; AK13 -8.5,-8.5; AK14 -7.5,-8.5; AK15 -6.5,-8.5; AK16 -5.5,-8.5; AK17 -4.5,-8.5; AK18 -3.5,-8.5; AK19 -2.5,-8.5; AK20 -1.5,-8.5; AK21 -0.5,-8.5; AK22 0.5,-8.5; AK23 1.5,-8.5; AK24 2.5,-8.5; AK25 3.5,-8.5; AK26 4.5,-8.5; AK27 5.5,-8.5; AK28 6.5,-8.5; AK29 7.5,-8.5; AK30 8.5,-8.5; AK31 9.5,-8.5; AK32 10.5,-8.5; AK33 11.5,-8.5; AK34 12.5,-8.5; AK35 13.5,-8.5; AK36 14.5,-8.5; AK37 15.5,-8.5; AK38 16.5,-8.5; AK39 17.5,-8.5; AK40 18.5,-8.5; AK41 19.5,-8.5; AK42 20.5,-8.5; AL1 -20.5,-9.5; AL2 -19.5,-9.5; AL3 -18.5,-9.5; AL4 -17.5,-9.5; AL5 -16.5,-9.5; AL6 -15.5,-9.5; AL7 -14.5,-9.5; AL8 -13.5,-9.5; AL9 -12.5,-9.5; AL10 -11.5,-9.5; AL11 -10.5,-9.5; AL12 -9.5,-9.5; AL13 -8.5,-9.5; AL14 -7.5,-9.5; AL15 -6.5,-9.5; AL16 -5.5,-9.5; AL17 -4.5,-9.5; AL18 -3.5,-9.5; AL19 -2.5,-9.5; AL20 -1.5,-9.5; AL21 -0.5,-9.5; AL22 0.5,-9.5; AL23 1.5,-9.5; AL24 2.5,-9.5; AL25 3.5,-9.5; AL26 4.5,-9.5; AL27 5.5,-9.5; AL28 6.5,-9.5; AL29 7.5,-9.5; AL30 8.5,-9.5; AL31 9.5,-9.5; AL32 10.5,-9.5; AL33 11.5,-9.5; AL34 12.5,-9.5; AL35 13.5,-9.5; AL36 14.5,-9.5; AL37 15.5,-9.5; AL38 16.5,-9.5; AL39 17.5,-9.5; AL40 18.5,-9.5; AL41 19.5,-9.5; AL42 20.5,-9.5; AM1 -20.5,-10.5; AM2 -19.5,-10.5; AM3 -18.5,-10.5; AM4 -17.5,-10.5; AM5 -16.5,-10.5; AM6 -15.5,-10.5; AM7 -14.5,-10.5; AM8 -13.5,-10.5; AM9 -12.5,-10.5; AM10 -11.5,-10.5; AM11 -10.5,-10.5; AM12 -9.5,-10.5; AM13 -8.5,-10.5; AM14 -7.5,-10.5; AM15 -6.5,-10.5; AM16 -5.5,-10.5; AM17 -4.5,-10.5; AM18 -3.5,-10.5; AM19 -2.5,-10.5; AM20 -1.5,-10.5; AM21 -0.5,-10.5; AM22 0.5,-10.5; AM23 1.5,-10.5; AM24 2.5,-10.5; AM25 3.5,-10.5; AM26 4.5,-10.5; AM27 5.5,-10.5; AM28 6.5,-10.5; AM29 7.5,-10.5; AM30 8.5,-10.5; AM31 9.5,-10.5; AM32 10.5,-10.5; AM33 11.5,-10.5; AM34 12.5,-10.5; AM35 13.5,-10.5; AM36 14.5,-10.5; AM37 15.5,-10.5; AM38 16.5,-10.5; AM39 17.5,-10.5; AM40 18.5,-10.5; AM41 19.5,-10.5; AM42 20.5,-10.5; AN2 -19.5,-11.5; AN3 -18.5,-11.5; AN4 -17.5,-11.5; AN5 -16.5,-11.5; AN6 -15.5,-11.5; AN7 -14.5,-11.5; AN8 -13.5,-11.5; AN9 -12.5,-11.5; AN10 -11.5,-11.5; AN11 -10.5,-11.5; AN12 -9.5,-11.5; AN13 -8.5,-11.5; AN14 -7.5,-11.5; AN15 -6.5,-11.5; AN16 -5.5,-11.5; AN17 -4.5,-11.5; AN18 -3.5,-11.5; AN19 -2.5,-11.5; AN20 -1.5,-11.5; AN21 -0.5,-11.5; AN22 0.5,-11.5; AN23 1.5,-11.5; AN24 2.5,-11.5; AN25 3.5,-11.5; AN26 4.5,-11.5; AN27 5.5,-11.5; AN28 6.5,-11.5; AN29 7.5,-11.5; AN30 8.5,-11.5; AN31 9.5,-11.5; AN32 10.5,-11.5; AN33 11.5,-11.5; AN34 12.5,-11.5; AN35 13.5,-11.5; AN36 14.5,-11.5; AN37 15.5,-11.5; AN38 16.5,-11.5; AN39 17.5,-11.5; AN40 18.5,-11.5; AN41 19.5,-11.5; AN42 20.5,-11.5; AP2 -19.5,-12.5; AP3 -18.5,-12.5; AP4 -17.5,-12.5; AP5 -16.5,-12.5; AP6 -15.5,-12.5; AP7 -14.5,-12.5; AP8 -13.5,-12.5; AP9 -12.5,-12.5; AP10 -11.5,-12.5; AP11 -10.5,-12.5; AP12 -9.5,-12.5; AP13 -8.5,-12.5; AP14 -7.5,-12.5; AP15 -6.5,-12.5; AP16 -5.5,-12.5; AP17 -4.5,-12.5; AP18 -3.5,-12.5; AP19 -2.5,-12.5; AP20 -1.5,-12.5; AP21 -0.5,-12.5; AP22 0.5,-12.5; AP23 1.5,-12.5; AP24 2.5,-12.5; AP25 3.5,-12.5; AP26 4.5,-12.5; AP27 5.5,-12.5; AP28 6.5,-12.5; AP29 7.5,-12.5; AP30 8.5,-12.5; AP31 9.5,-12.5; AP32 10.5,-12.5; AP33 11.5,-12.5; AP34 12.5,-12.5; AP35 13.5,-12.5; AP36 14.5,-12.5; AP37 15.5,-12.5; AP38 16.5,-12.5; AP39 17.5,-12.5; AP40 18.5,-12.5; AP41 19.5,-12.5; AP42 20.5,-12.5; AR1 -20.5,-13.5; AR2 -19.5,-13.5; AR3 -18.5,-13.5; AR4 -17.5,-13.5; AR5 -16.5,-13.5; AR6 -15.5,-13.5; AR7 -14.5,-13.5; AR8 -13.5,-13.5; AR9 -12.5,-13.5; AR10 -11.5,-13.5; AR11 -10.5,-13.5; AR12 -9.5,-13.5; AR13 -8.5,-13.5; AR14 -7.5,-13.5; AR15 -6.5,-13.5; AR16 -5.5,-13.5; AR17 -4.5,-13.5; AR18 -3.5,-13.5; AR19 -2.5,-13.5; AR20 -1.5,-13.5; AR21 -0.5,-13.5; AR22 0.5,-13.5; AR23 1.5,-13.5; AR24 2.5,-13.5; AR25 3.5,-13.5; AR26 4.5,-13.5; AR27 5.5,-13.5; AR28 6.5,-13.5; AR29 7.5,-13.5; AR30 8.5,-13.5; AR31 9.5,-13.5; AR32 10.5,-13.5; AR33 11.5,-13.5; AR34 12.5,-13.5; AR35 13.5,-13.5; AR36 14.5,-13.5; AR37 15.5,-13.5; AR38 16.5,-13.5; AR39 17.5,-13.5; AR40 18.5,-13.5; AR41 19.5,-13.5; AR42 20.5,-13.5; AT1 -20.5,-14.5; AT2 -19.5,-14.5; AT3 -18.5,-14.5; AT4 -17.5,-14.5; AT5 -16.5,-14.5; AT6 -15.5,-14.5; AT7 -14.5,-14.5; AT8 -13.5,-14.5; AT9 -12.5,-14.5; AT10 -11.5,-14.5; AT11 -10.5,-14.5; AT12 -9.5,-14.5; AT13 -8.5,-14.5; AT14 -7.5,-14.5; AT15 -6.5,-14.5; AT16 -5.5,-14.5; AT17 -4.5,-14.5; AT18 -3.5,-14.5; AT19 -2.5,-14.5; AT20 -1.5,-14.5; AT21 -0.5,-14.5; AT22 0.5,-14.5; AT23 1.5,-14.5; AT24 2.5,-14.5; AT25 3.5,-14.5; AT26 4.5,-14.5; AT27 5.5,-14.5; AT28 6.5,-14.5; AT29 7.5,-14.5; AT30 8.5,-14.5; AT31 9.5,-14.5; AT32 10.5,-14.5; AT33 11.5,-14.5; AT34 12.5,-14.5; AT35 13.5,-14.5; AT36 14.5,-14.5; AT37 15.5,-14.5; AT38 16.5,-14.5; AT39 17.5,-14.5; AT40 18.5,-14.5; AT41 19.5,-14.5; AT42 20.5,-14.5; AU1 -20.5,-15.5; AU2 -19.5,-15.5; AU3 -18.5,-15.5; AU4 -17.5,-15.5; AU5 -16.5,-15.5; AU6 -15.5,-15.5; AU7 -14.5,-15.5; AU8 -13.5,-15.5; AU9 -12.5,-15.5; AU10 -11.5,-15.5; AU11 -10.5,-15.5; AU12 -9.5,-15.5; AU13 -8.5,-15.5; AU14 -7.5,-15.5; AU15 -6.5,-15.5; AU16 -5.5,-15.5; AU17 -4.5,-15.5; AU18 -3.5,-15.5; AU19 -2.5,-15.5; AU20 -1.5,-15.5; AU21 -0.5,-15.5; AU22 0.5,-15.5; AU23 1.5,-15.5; AU24 2.5,-15.5; AU25 3.5,-15.5; AU26 4.5,-15.5; AU27 5.5,-15.5; AU28 6.5,-15.5; AU29 7.5,-15.5; AU30 8.5,-15.5; AU31 9.5,-15.5; AU32 10.5,-15.5; AU33 11.5,-15.5; AU34 12.5,-15.5; AU35 13.5,-15.5; AU36 14.5,-15.5; AU37 15.5,-15.5; AU38 16.5,-15.5; AU39 17.5,-15.5; AU40 18.5,-15.5; AU41 19.5,-15.5; AU42 20.5,-15.5; AV1 -20.5,-16.5; AV2 -19.5,-16.5; AV3 -18.5,-16.5; AV4 -17.5,-16.5; AV5 -16.5,-16.5; AV6 -15.5,-16.5; AV7 -14.5,-16.5; AV8 -13.5,-16.5; AV9 -12.5,-16.5; AV10 -11.5,-16.5; AV11 -10.5,-16.5; AV12 -9.5,-16.5; AV13 -8.5,-16.5; AV14 -7.5,-16.5; AV15 -6.5,-16.5; AV16 -5.5,-16.5; AV17 -4.5,-16.5; AV18 -3.5,-16.5; AV19 -2.5,-16.5; AV20 -1.5,-16.5; AV21 -0.5,-16.5; AV22 0.5,-16.5; AV23 1.5,-16.5; AV24 2.5,-16.5; AV25 3.5,-16.5; AV26 4.5,-16.5; AV27 5.5,-16.5; AV28 6.5,-16.5; AV29 7.5,-16.5; AV30 8.5,-16.5; AV31 9.5,-16.5; AV32 10.5,-16.5; AV33 11.5,-16.5; AV34 12.5,-16.5; AV35 13.5,-16.5; AV36 14.5,-16.5; AV37 15.5,-16.5; AV38 16.5,-16.5; AV39 17.5,-16.5; AV40 18.5,-16.5; AV41 19.5,-16.5; AV42 20.5,-16.5; AW2 -19.5,-17.5; AW3 -18.5,-17.5; AW4 -17.5,-17.5; AW5 -16.5,-17.5; AW6 -15.5,-17.5; AW7 -14.5,-17.5; AW8 -13.5,-17.5; AW9 -12.5,-17.5; AW10 -11.5,-17.5; AW11 -10.5,-17.5; AW12 -9.5,-17.5; AW13 -8.5,-17.5; AW14 -7.5,-17.5; AW15 -6.5,-17.5; AW16 -5.5,-17.5; AW17 -4.5,-17.5; AW18 -3.5,-17.5; AW19 -2.5,-17.5; AW20 -1.5,-17.5; AW21 -0.5,-17.5; AW22 0.5,-17.5; AW23 1.5,-17.5; AW24 2.5,-17.5; AW25 3.5,-17.5; AW26 4.5,-17.5; AW27 5.5,-17.5; AW28 6.5,-17.5; AW29 7.5,-17.5; AW30 8.5,-17.5; AW31 9.5,-17.5; AW32 10.5,-17.5; AW33 11.5,-17.5; AW34 12.5,-17.5; AW35 13.5,-17.5; AW36 14.5,-17.5; AW37 15.5,-17.5; AW38 16.5,-17.5; AW39 17.5,-17.5; AW40 18.5,-17.5; AW41 19.5,-17.5; AW42 20.5,-17.5; AY1 -20.5,-18.5; AY2 -19.5,-18.5; AY3 -18.5,-18.5; AY4 -17.5,-18.5; AY5 -16.5,-18.5; AY6 -15.5,-18.5; AY7 -14.5,-18.5; AY8 -13.5,-18.5; AY9 -12.5,-18.5; AY10 -11.5,-18.5; AY11 -10.5,-18.5; AY12 -9.5,-18.5; AY13 -8.5,-18.5; AY14 -7.5,-18.5; AY15 -6.5,-18.5; AY16 -5.5,-18.5; AY17 -4.5,-18.5; AY18 -3.5,-18.5; AY19 -2.5,-18.5; AY20 -1.5,-18.5; AY21 -0.5,-18.5; AY22 0.5,-18.5; AY23 1.5,-18.5; AY24 2.5,-18.5; AY25 3.5,-18.5; AY26 4.5,-18.5; AY27 5.5,-18.5; AY28 6.5,-18.5; AY29 7.5,-18.5; AY30 8.5,-18.5; AY31 9.5,-18.5; AY32 10.5,-18.5; AY33 11.5,-18.5; AY34 12.5,-18.5; AY35 13.5,-18.5; AY36 14.5,-18.5; AY37 15.5,-18.5; AY38 16.5,-18.5; AY39 17.5,-18.5; AY40 18.5,-18.5; AY41 19.5,-18.5; AY42 20.5,-18.5; B1 -20.5,19.5; B2 -19.5,19.5; B3 -18.5,19.5; B4 -17.5,19.5; B5 -16.5,19.5; B6 -15.5,19.5; B7 -14.5,19.5; B8 -13.5,19.5; B9 -12.5,19.5; B10 -11.5,19.5; B11 -10.5,19.5; B12 -9.5,19.5; B13 -8.5,19.5; B14 -7.5,19.5; B15 -6.5,19.5; B16 -5.5,19.5; B17 -4.5,19.5; B18 -3.5,19.5; B19 -2.5,19.5; B20 -1.5,19.5; B21 -0.5,19.5; B22 0.5,19.5; B23 1.5,19.5; B24 2.5,19.5; B25 3.5,19.5; B26 4.5,19.5; B27 5.5,19.5; B28 6.5,19.5; B29 7.5,19.5; B30 8.5,19.5; B31 9.5,19.5; B32 10.5,19.5; B33 11.5,19.5; B34 12.5,19.5; B35 13.5,19.5; B36 14.5,19.5; B37 15.5,19.5; B38 16.5,19.5; B39 17.5,19.5; B40 18.5,19.5; B41 19.5,19.5; B42 20.5,19.5; BA1 -20.5,-19.5; BA2 -19.5,-19.5; BA3 -18.5,-19.5; BA4 -17.5,-19.5; BA5 -16.5,-19.5; BA6 -15.5,-19.5; BA7 -14.5,-19.5; BA8 -13.5,-19.5; BA9 -12.5,-19.5; BA10 -11.5,-19.5; BA11 -10.5,-19.5; BA12 -9.5,-19.5; BA13 -8.5,-19.5; BA14 -7.5,-19.5; BA15 -6.5,-19.5; BA16 -5.5,-19.5; BA17 -4.5,-19.5; BA18 -3.5,-19.5; BA19 -2.5,-19.5; BA20 -1.5,-19.5; BA21 -0.5,-19.5; BA22 0.5,-19.5; BA23 1.5,-19.5; BA24 2.5,-19.5; BA25 3.5,-19.5; BA26 4.5,-19.5; BA27 5.5,-19.5; BA28 6.5,-19.5; BA29 7.5,-19.5; BA30 8.5,-19.5; BA31 9.5,-19.5; BA32 10.5,-19.5; BA33 11.5,-19.5; BA34 12.5,-19.5; BA35 13.5,-19.5; BA36 14.5,-19.5; BA37 15.5,-19.5; BA38 16.5,-19.5; BA39 17.5,-19.5; BA40 18.5,-19.5; BA41 19.5,-19.5; BA42 20.5,-19.5; BB2 -19.5,-20.5; BB3 -18.5,-20.5; BB4 -17.5,-20.5; BB5 -16.5,-20.5; BB8 -13.5,-20.5; BB9 -12.5,-20.5; BB10 -11.5,-20.5; BB11 -10.5,-20.5; BB14 -7.5,-20.5; BB15 -6.5,-20.5; BB16 -5.5,-20.5; BB17 -4.5,-20.5; BB19 -2.5,-20.5; BB20 -1.5,-20.5; BB21 -0.5,-20.5; BB22 0.5,-20.5; BB23 1.5,-20.5; BB24 2.5,-20.5; BB25 3.5,-20.5; BB26 4.5,-20.5; BB27 5.5,-20.5; BB28 6.5,-20.5; BB29 7.5,-20.5; BB30 8.5,-20.5; BB31 9.5,-20.5; BB32 10.5,-20.5; BB33 11.5,-20.5; BB34 12.5,-20.5; BB35 13.5,-20.5; BB36 14.5,-20.5; BB37 15.5,-20.5; BB38 16.5,-20.5; BB39 17.5,-20.5; BB40 18.5,-20.5; BB41 19.5,-20.5; C1 -20.5,18.5; C2 -19.5,18.5; C3 -18.5,18.5; C4 -17.5,18.5; C5 -16.5,18.5; C6 -15.5,18.5; C7 -14.5,18.5; C8 -13.5,18.5; C9 -12.5,18.5; C10 -11.5,18.5; C11 -10.5,18.5; C12 -9.5,18.5; C13 -8.5,18.5; C14 -7.5,18.5; C15 -6.5,18.5; C16 -5.5,18.5; C17 -4.5,18.5; C18 -3.5,18.5; C19 -2.5,18.5; C20 -1.5,18.5; C21 -0.5,18.5; C22 0.5,18.5; C23 1.5,18.5; C24 2.5,18.5; C25 3.5,18.5; C26 4.5,18.5; C27 5.5,18.5; C28 6.5,18.5; C29 7.5,18.5; C30 8.5,18.5; C31 9.5,18.5; C32 10.5,18.5; C33 11.5,18.5; C34 12.5,18.5; C35 13.5,18.5; C36 14.5,18.5; C37 15.5,18.5; C38 16.5,18.5; C39 17.5,18.5; C40 18.5,18.5; C41 19.5,18.5; C42 20.5,18.5; D2 -19.5,17.5; D3 -18.5,17.5; D4 -17.5,17.5; D5 -16.5,17.5; D6 -15.5,17.5; D7 -14.5,17.5; D8 -13.5,17.5; D9 -12.5,17.5; D10 -11.5,17.5; D11 -10.5,17.5; D12 -9.5,17.5; D13 -8.5,17.5; D14 -7.5,17.5; D15 -6.5,17.5; D16 -5.5,17.5; D17 -4.5,17.5; D18 -3.5,17.5; D19 -2.5,17.5; D20 -1.5,17.5; D21 -0.5,17.5; D22 0.5,17.5; D23 1.5,17.5; D24 2.5,17.5; D25 3.5,17.5; D26 4.5,17.5; D27 5.5,17.5; D28 6.5,17.5; D29 7.5,17.5; D30 8.5,17.5; D31 9.5,17.5; D32 10.5,17.5; D33 11.5,17.5; D34 12.5,17.5; D35 13.5,17.5; D36 14.5,17.5; D37 15.5,17.5; D38 16.5,17.5; D39 17.5,17.5; D40 18.5,17.5; D41 19.5,17.5; D42 20.5,17.5; E1 -20.5,16.5; E2 -19.5,16.5; E3 -18.5,16.5; E4 -17.5,16.5; E5 -16.5,16.5; E6 -15.5,16.5; E7 -14.5,16.5; E8 -13.5,16.5; E9 -12.5,16.5; E10 -11.5,16.5; E11 -10.5,16.5; E12 -9.5,16.5; E13 -8.5,16.5; E14 -7.5,16.5; E15 -6.5,16.5; E16 -5.5,16.5; E17 -4.5,16.5; E18 -3.5,16.5; E19 -2.5,16.5; E20 -1.5,16.5; E21 -0.5,16.5; E22 0.5,16.5; E23 1.5,16.5; E24 2.5,16.5; E25 3.5,16.5; E26 4.5,16.5; E27 5.5,16.5; E28 6.5,16.5; E29 7.5,16.5; E30 8.5,16.5; E31 9.5,16.5; E32 10.5,16.5; E33 11.5,16.5; E34 12.5,16.5; E35 13.5,16.5; E36 14.5,16.5; E37 15.5,16.5; E38 16.5,16.5; E39 17.5,16.5; E40 18.5,16.5; E41 19.5,16.5; E42 20.5,16.5; F1 -20.5,15.5; F2 -19.5,15.5; F3 -18.5,15.5; F4 -17.5,15.5; F5 -16.5,15.5; F6 -15.5,15.5; F7 -14.5,15.5; F8 -13.5,15.5; F9 -12.5,15.5; F10 -11.5,15.5; F11 -10.5,15.5; F12 -9.5,15.5; F13 -8.5,15.5; F14 -7.5,15.5; F15 -6.5,15.5; F16 -5.5,15.5; F17 -4.5,15.5; F18 -3.5,15.5; F19 -2.5,15.5; F20 -1.5,15.5; F21 -0.5,15.5; F22 0.5,15.5; F23 1.5,15.5; F24 2.5,15.5; F25 3.5,15.5; F26 4.5,15.5; F27 5.5,15.5; F28 6.5,15.5; F29 7.5,15.5; F30 8.5,15.5; F31 9.5,15.5; F32 10.5,15.5; F33 11.5,15.5; F34 12.5,15.5; F35 13.5,15.5; F36 14.5,15.5; F37 15.5,15.5; F38 16.5,15.5; F39 17.5,15.5; F40 18.5,15.5; F41 19.5,15.5; F42 20.5,15.5; G1 -20.5,14.5; G2 -19.5,14.5; G3 -18.5,14.5; G4 -17.5,14.5; G5 -16.5,14.5; G6 -15.5,14.5; G7 -14.5,14.5; G8 -13.5,14.5; G9 -12.5,14.5; G10 -11.5,14.5; G11 -10.5,14.5; G12 -9.5,14.5; G13 -8.5,14.5; G14 -7.5,14.5; G15 -6.5,14.5; G16 -5.5,14.5; G17 -4.5,14.5; G18 -3.5,14.5; G19 -2.5,14.5; G20 -1.5,14.5; G21 -0.5,14.5; G22 0.5,14.5; G23 1.5,14.5; G24 2.5,14.5; G25 3.5,14.5; G26 4.5,14.5; G27 5.5,14.5; G28 6.5,14.5; G29 7.5,14.5; G30 8.5,14.5; G31 9.5,14.5; G32 10.5,14.5; G33 11.5,14.5; G34 12.5,14.5; G35 13.5,14.5; G36 14.5,14.5; G37 15.5,14.5; G38 16.5,14.5; G39 17.5,14.5; G40 18.5,14.5; G41 19.5,14.5; G42 20.5,14.5; H1 -20.5,13.5; H2 -19.5,13.5; H3 -18.5,13.5; H4 -17.5,13.5; H5 -16.5,13.5; H6 -15.5,13.5; H7 -14.5,13.5; H8 -13.5,13.5; H9 -12.5,13.5; H10 -11.5,13.5; H11 -10.5,13.5; H12 -9.5,13.5; H13 -8.5,13.5; H14 -7.5,13.5; H15 -6.5,13.5; H16 -5.5,13.5; H17 -4.5,13.5; H18 -3.5,13.5; H19 -2.5,13.5; H20 -1.5,13.5; H21 -0.5,13.5; H22 0.5,13.5; H23 1.5,13.5; H24 2.5,13.5; H25 3.5,13.5; H26 4.5,13.5; H27 5.5,13.5; H28 6.5,13.5; H29 7.5,13.5; H30 8.5,13.5; H31 9.5,13.5; H32 10.5,13.5; H33 11.5,13.5; H34 12.5,13.5; H35 13.5,13.5; H36 14.5,13.5; H37 15.5,13.5; H38 16.5,13.5; H39 17.5,13.5; H40 18.5,13.5; H41 19.5,13.5; H42 20.5,13.5; J2 -19.5,12.5; J3 -18.5,12.5; J4 -17.5,12.5; J5 -16.5,12.5; J6 -15.5,12.5; J7 -14.5,12.5; J8 -13.5,12.5; J9 -12.5,12.5; J10 -11.5,12.5; J11 -10.5,12.5; J12 -9.5,12.5; J13 -8.5,12.5; J14 -7.5,12.5; J15 -6.5,12.5; J16 -5.5,12.5; J17 -4.5,12.5; J18 -3.5,12.5; J19 -2.5,12.5; J20 -1.5,12.5; J21 -0.5,12.5; J22 0.5,12.5; J23 1.5,12.5; J24 2.5,12.5; J25 3.5,12.5; J26 4.5,12.5; J27 5.5,12.5; J28 6.5,12.5; J29 7.5,12.5; J30 8.5,12.5; J31 9.5,12.5; J32 10.5,12.5; J33 11.5,12.5; J34 12.5,12.5; J35 13.5,12.5; J36 14.5,12.5; J37 15.5,12.5; J38 16.5,12.5; J39 17.5,12.5; J40 18.5,12.5; J41 19.5,12.5; J42 20.5,12.5; K2 -19.5,11.5; K3 -18.5,11.5; K4 -17.5,11.5; K5 -16.5,11.5; K6 -15.5,11.5; K7 -14.5,11.5; K8 -13.5,11.5; K9 -12.5,11.5; K10 -11.5,11.5; K11 -10.5,11.5; K12 -9.5,11.5; K13 -8.5,11.5; K14 -7.5,11.5; K15 -6.5,11.5; K16 -5.5,11.5; K17 -4.5,11.5; K18 -3.5,11.5; K19 -2.5,11.5; K20 -1.5,11.5; K21 -0.5,11.5; K22 0.5,11.5; K23 1.5,11.5; K24 2.5,11.5; K25 3.5,11.5; K26 4.5,11.5; K27 5.5,11.5; K28 6.5,11.5; K29 7.5,11.5; K30 8.5,11.5; K31 9.5,11.5; K32 10.5,11.5; K33 11.5,11.5; K34 12.5,11.5; K35 13.5,11.5; K36 14.5,11.5; K37 15.5,11.5; K38 16.5,11.5; K39 17.5,11.5; K40 18.5,11.5; K41 19.5,11.5; K42 20.5,11.5; L1 -20.5,10.5; L2 -19.5,10.5; L3 -18.5,10.5; L4 -17.5,10.5; L5 -16.5,10.5; L6 -15.5,10.5; L7 -14.5,10.5; L8 -13.5,10.5; L9 -12.5,10.5; L10 -11.5,10.5; L11 -10.5,10.5; L12 -9.5,10.5; L13 -8.5,10.5; L14 -7.5,10.5; L15 -6.5,10.5; L16 -5.5,10.5; L17 -4.5,10.5; L18 -3.5,10.5; L19 -2.5,10.5; L20 -1.5,10.5; L21 -0.5,10.5; L22 0.5,10.5; L23 1.5,10.5; L24 2.5,10.5; L25 3.5,10.5; L26 4.5,10.5; L27 5.5,10.5; L28 6.5,10.5; L29 7.5,10.5; L30 8.5,10.5; L31 9.5,10.5; L32 10.5,10.5; L33 11.5,10.5; L34 12.5,10.5; L35 13.5,10.5; L36 14.5,10.5; L37 15.5,10.5; L38 16.5,10.5; L39 17.5,10.5; L40 18.5,10.5; L41 19.5,10.5; L42 20.5,10.5; M1 -20.5,9.5; M2 -19.5,9.5; M3 -18.5,9.5; M4 -17.5,9.5; M5 -16.5,9.5; M6 -15.5,9.5; M7 -14.5,9.5; M8 -13.5,9.5; M9 -12.5,9.5; M10 -11.5,9.5; M11 -10.5,9.5; M12 -9.5,9.5; M13 -8.5,9.5; M14 -7.5,9.5; M15 -6.5,9.5; M16 -5.5,9.5; M17 -4.5,9.5; M18 -3.5,9.5; M19 -2.5,9.5; M20 -1.5,9.5; M21 -0.5,9.5; M22 0.5,9.5; M23 1.5,9.5; M24 2.5,9.5; M25 3.5,9.5; M26 4.5,9.5; M27 5.5,9.5; M28 6.5,9.5; M29 7.5,9.5; M30 8.5,9.5; M31 9.5,9.5; M32 10.5,9.5; M33 11.5,9.5; M34 12.5,9.5; M35 13.5,9.5; M36 14.5,9.5; M37 15.5,9.5; M38 16.5,9.5; M39 17.5,9.5; M40 18.5,9.5; M41 19.5,9.5; M42 20.5,9.5; N1 -20.5,8.5; N2 -19.5,8.5; N3 -18.5,8.5; N4 -17.5,8.5; N5 -16.5,8.5; N6 -15.5,8.5; N7 -14.5,8.5; N8 -13.5,8.5; N9 -12.5,8.5; N10 -11.5,8.5; N11 -10.5,8.5; N12 -9.5,8.5; N13 -8.5,8.5; N14 -7.5,8.5; N15 -6.5,8.5; N16 -5.5,8.5; N17 -4.5,8.5; N18 -3.5,8.5; N19 -2.5,8.5; N20 -1.5,8.5; N21 -0.5,8.5; N22 0.5,8.5; N23 1.5,8.5; N24 2.5,8.5; N25 3.5,8.5; N26 4.5,8.5; N27 5.5,8.5; N28 6.5,8.5; N29 7.5,8.5; N30 8.5,8.5; N31 9.5,8.5; N32 10.5,8.5; N33 11.5,8.5; N34 12.5,8.5; N35 13.5,8.5; N36 14.5,8.5; N37 15.5,8.5; N38 16.5,8.5; N39 17.5,8.5; N40 18.5,8.5; N41 19.5,8.5; N42 20.5,8.5; P1 -20.5,7.5; P2 -19.5,7.5; P3 -18.5,7.5; P4 -17.5,7.5; P5 -16.5,7.5; P6 -15.5,7.5; P7 -14.5,7.5; P8 -13.5,7.5; P9 -12.5,7.5; P10 -11.5,7.5; P11 -10.5,7.5; P12 -9.5,7.5; P13 -8.5,7.5; P14 -7.5,7.5; P15 -6.5,7.5; P16 -5.5,7.5; P17 -4.5,7.5; P18 -3.5,7.5; P19 -2.5,7.5; P20 -1.5,7.5; P21 -0.5,7.5; P22 0.5,7.5; P23 1.5,7.5; P24 2.5,7.5; P25 3.5,7.5; P26 4.5,7.5; P27 5.5,7.5; P28 6.5,7.5; P29 7.5,7.5; P30 8.5,7.5; P31 9.5,7.5; P32 10.5,7.5; P33 11.5,7.5; P34 12.5,7.5; P35 13.5,7.5; P36 14.5,7.5; P37 15.5,7.5; P38 16.5,7.5; P39 17.5,7.5; P40 18.5,7.5; P41 19.5,7.5; P42 20.5,7.5; R2 -19.5,6.5; R3 -18.5,6.5; R4 -17.5,6.5; R5 -16.5,6.5; R6 -15.5,6.5; R7 -14.5,6.5; R8 -13.5,6.5; R9 -12.5,6.5; R10 -11.5,6.5; R11 -10.5,6.5; R12 -9.5,6.5; R13 -8.5,6.5; R14 -7.5,6.5; R15 -6.5,6.5; R16 -5.5,6.5; R17 -4.5,6.5; R18 -3.5,6.5; R19 -2.5,6.5; R20 -1.5,6.5; R21 -0.5,6.5; R22 0.5,6.5; R23 1.5,6.5; R24 2.5,6.5; R25 3.5,6.5; R26 4.5,6.5; R27 5.5,6.5; R28 6.5,6.5; R29 7.5,6.5; R30 8.5,6.5; R31 9.5,6.5; R32 10.5,6.5; R33 11.5,6.5; R34 12.5,6.5; R35 13.5,6.5; R36 14.5,6.5; R37 15.5,6.5; R38 16.5,6.5; R39 17.5,6.5; R40 18.5,6.5; R41 19.5,6.5; R42 20.5,6.5; T2 -19.5,5.5; T3 -18.5,5.5; T4 -17.5,5.5; T5 -16.5,5.5; T6 -15.5,5.5; T7 -14.5,5.5; T8 -13.5,5.5; T9 -12.5,5.5; T10 -11.5,5.5; T11 -10.5,5.5; T12 -9.5,5.5; T13 -8.5,5.5; T14 -7.5,5.5; T15 -6.5,5.5; T16 -5.5,5.5; T17 -4.5,5.5; T18 -3.5,5.5; T19 -2.5,5.5; T20 -1.5,5.5; T21 -0.5,5.5; T22 0.5,5.5; T23 1.5,5.5; T24 2.5,5.5; T25 3.5,5.5; T26 4.5,5.5; T27 5.5,5.5; T28 6.5,5.5; T29 7.5,5.5; T30 8.5,5.5; T31 9.5,5.5; T32 10.5,5.5; T33 11.5,5.5; T34 12.5,5.5; T35 13.5,5.5; T36 14.5,5.5; T37 15.5,5.5; T38 16.5,5.5; T39 17.5,5.5; T40 18.5,5.5; T41 19.5,5.5; T42 20.5,5.5; U1 -20.5,4.5; U2 -19.5,4.5; U3 -18.5,4.5; U4 -17.5,4.5; U5 -16.5,4.5; U6 -15.5,4.5; U7 -14.5,4.5; U8 -13.5,4.5; U9 -12.5,4.5; U10 -11.5,4.5; U11 -10.5,4.5; U12 -9.5,4.5; U13 -8.5,4.5; U14 -7.5,4.5; U15 -6.5,4.5; U16 -5.5,4.5; U17 -4.5,4.5; U18 -3.5,4.5; U19 -2.5,4.5; U20 -1.5,4.5; U21 -0.5,4.5; U22 0.5,4.5; U23 1.5,4.5; U24 2.5,4.5; U25 3.5,4.5; U26 4.5,4.5; U27 5.5,4.5; U28 6.5,4.5; U29 7.5,4.5; U30 8.5,4.5; U31 9.5,4.5; U32 10.5,4.5; U33 11.5,4.5; U34 12.5,4.5; U35 13.5,4.5; U36 14.5,4.5; U37 15.5,4.5; U38 16.5,4.5; U39 17.5,4.5; U40 18.5,4.5; U41 19.5,4.5; U42 20.5,4.5; V1 -20.5,3.5; V2 -19.5,3.5; V3 -18.5,3.5; V4 -17.5,3.5; V5 -16.5,3.5; V6 -15.5,3.5; V7 -14.5,3.5; V8 -13.5,3.5; V9 -12.5,3.5; V10 -11.5,3.5; V11 -10.5,3.5; V12 -9.5,3.5; V13 -8.5,3.5; V14 -7.5,3.5; V15 -6.5,3.5; V16 -5.5,3.5; V17 -4.5,3.5; V18 -3.5,3.5; V19 -2.5,3.5; V20 -1.5,3.5; V21 -0.5,3.5; V22 0.5,3.5; V23 1.5,3.5; V24 2.5,3.5; V25 3.5,3.5; V26 4.5,3.5; V27 5.5,3.5; V28 6.5,3.5; V29 7.5,3.5; V30 8.5,3.5; V31 9.5,3.5; V32 10.5,3.5; V33 11.5,3.5; V34 12.5,3.5; V35 13.5,3.5; V36 14.5,3.5; V37 15.5,3.5; V38 16.5,3.5; V39 17.5,3.5; V40 18.5,3.5; V41 19.5,3.5; V42 20.5,3.5; W1 -20.5,2.5; W2 -19.5,2.5; W3 -18.5,2.5; W4 -17.5,2.5; W5 -16.5,2.5; W6 -15.5,2.5; W7 -14.5,2.5; W8 -13.5,2.5; W9 -12.5,2.5; W10 -11.5,2.5; W11 -10.5,2.5; W12 -9.5,2.5; W13 -8.5,2.5; W14 -7.5,2.5; W15 -6.5,2.5; W16 -5.5,2.5; W17 -4.5,2.5; W18 -3.5,2.5; W19 -2.5,2.5; W20 -1.5,2.5; W21 -0.5,2.5; W22 0.5,2.5; W23 1.5,2.5; W24 2.5,2.5; W25 3.5,2.5; W26 4.5,2.5; W27 5.5,2.5; W28 6.5,2.5; W29 7.5,2.5; W30 8.5,2.5; W31 9.5,2.5; W32 10.5,2.5; W33 11.5,2.5; W34 12.5,2.5; W35 13.5,2.5; W36 14.5,2.5; W37 15.5,2.5; W38 16.5,2.5; W39 17.5,2.5; W40 18.5,2.5; W41 19.5,2.5; W42 20.5,2.5; Y1 -20.5,1.5; Y2 -19.5,1.5; Y3 -18.5,1.5; Y4 -17.5,1.5; Y5 -16.5,1.5; Y6 -15.5,1.5; Y7 -14.5,1.5; Y8 -13.5,1.5; Y9 -12.5,1.5; Y10 -11.5,1.5; Y11 -10.5,1.5; Y12 -9.5,1.5; Y13 -8.5,1.5; Y14 -7.5,1.5; Y15 -6.5,1.5; Y16 -5.5,1.5; Y17 -4.5,1.5; Y18 -3.5,1.5; Y19 -2.5,1.5; Y20 -1.5,1.5; Y21 -0.5,1.5; Y22 0.5,1.5; Y23 1.5,1.5; Y24 2.5,1.5; Y25 3.5,1.5; Y26 4.5,1.5; Y27 5.5,1.5; Y28 6.5,1.5; Y29 7.5,1.5; Y30 8.5,1.5; Y31 9.5,1.5; Y32 10.5,1.5; Y33 11.5,1.5; Y34 12.5,1.5; Y35 13.5,1.5; Y36 14.5,1.5; Y37 15.5,1.5; Y38 16.5,1.5; Y39 17.5,1.5; Y40 18.5,1.5; Y41 19.5,1.5; Y42 20.5,1.5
